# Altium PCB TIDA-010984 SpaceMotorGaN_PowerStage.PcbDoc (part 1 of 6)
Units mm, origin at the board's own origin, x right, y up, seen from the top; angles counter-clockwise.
Board outline 177.8 x 152.4 mm, 8 copper layers (Top Layer, DC LINK Layer 2, GND Layer 3, 3V3 Layer 4, Layer 5, Layer 6, GND Layer 7, Bottom Layer), stack 1.554 mm thick; 582 components, 280 nets, 1847 pads, 979 vias.
Unrouted connection lines stored in the file: 474.
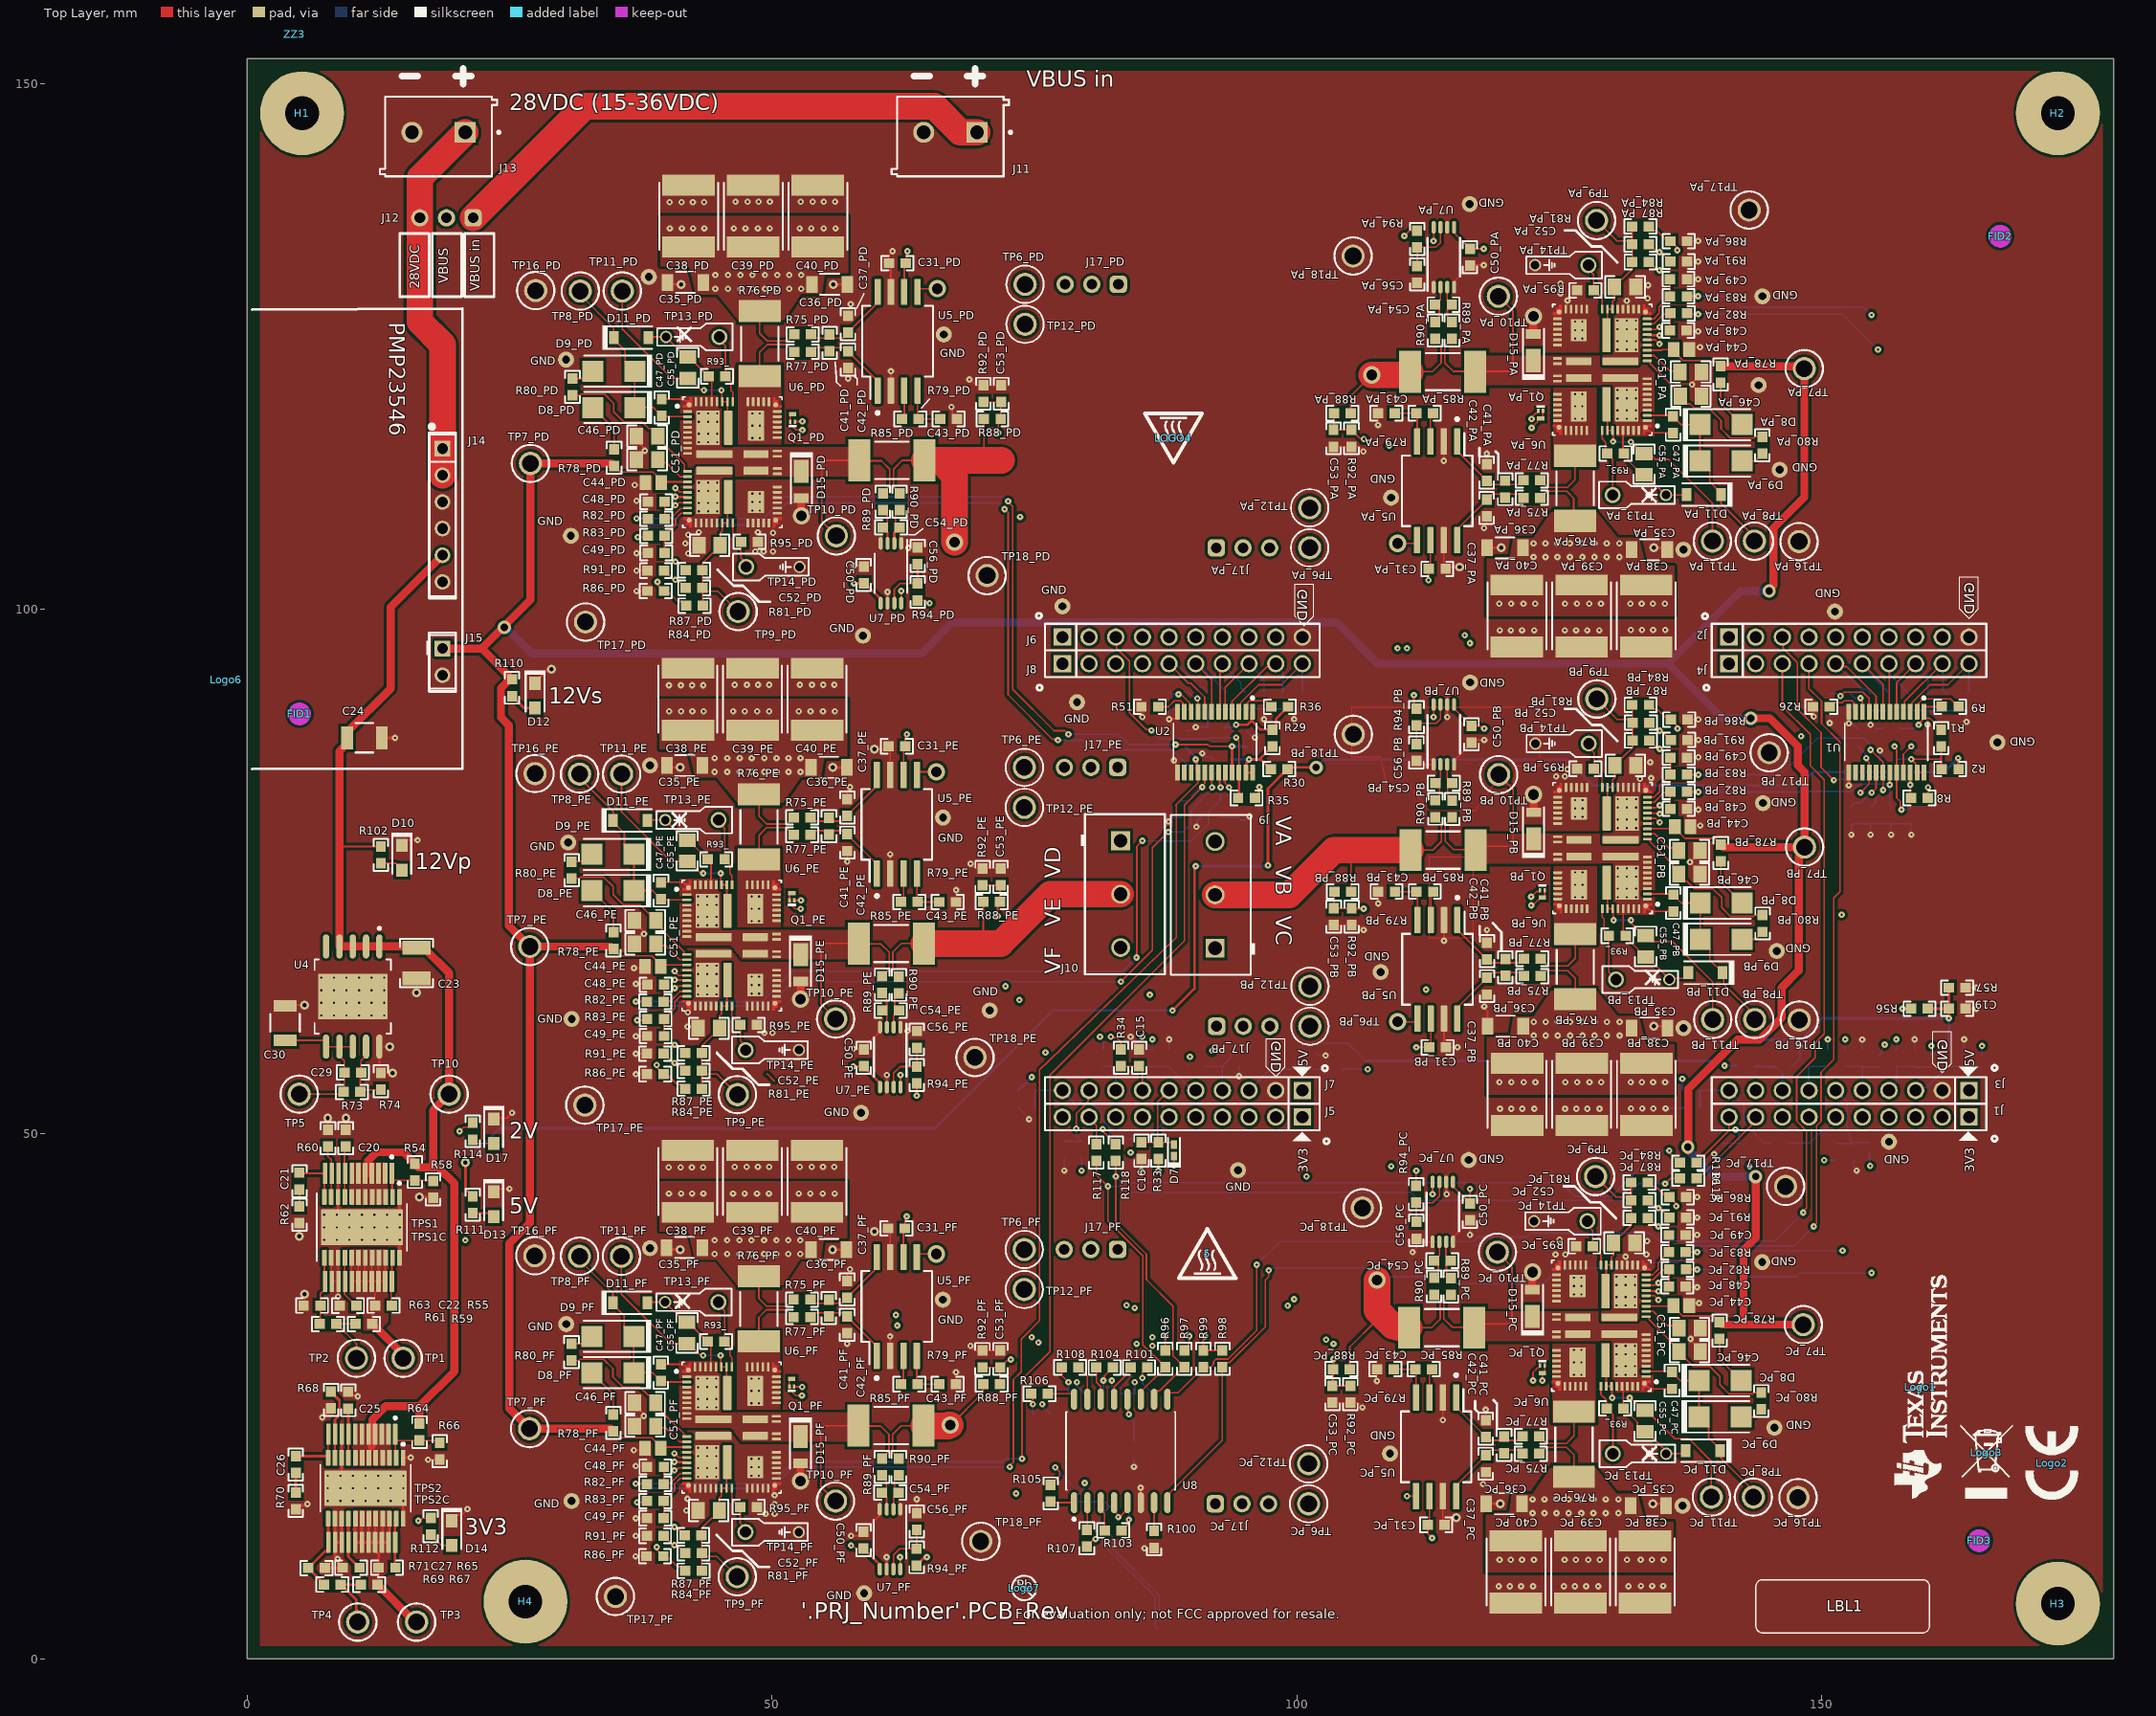
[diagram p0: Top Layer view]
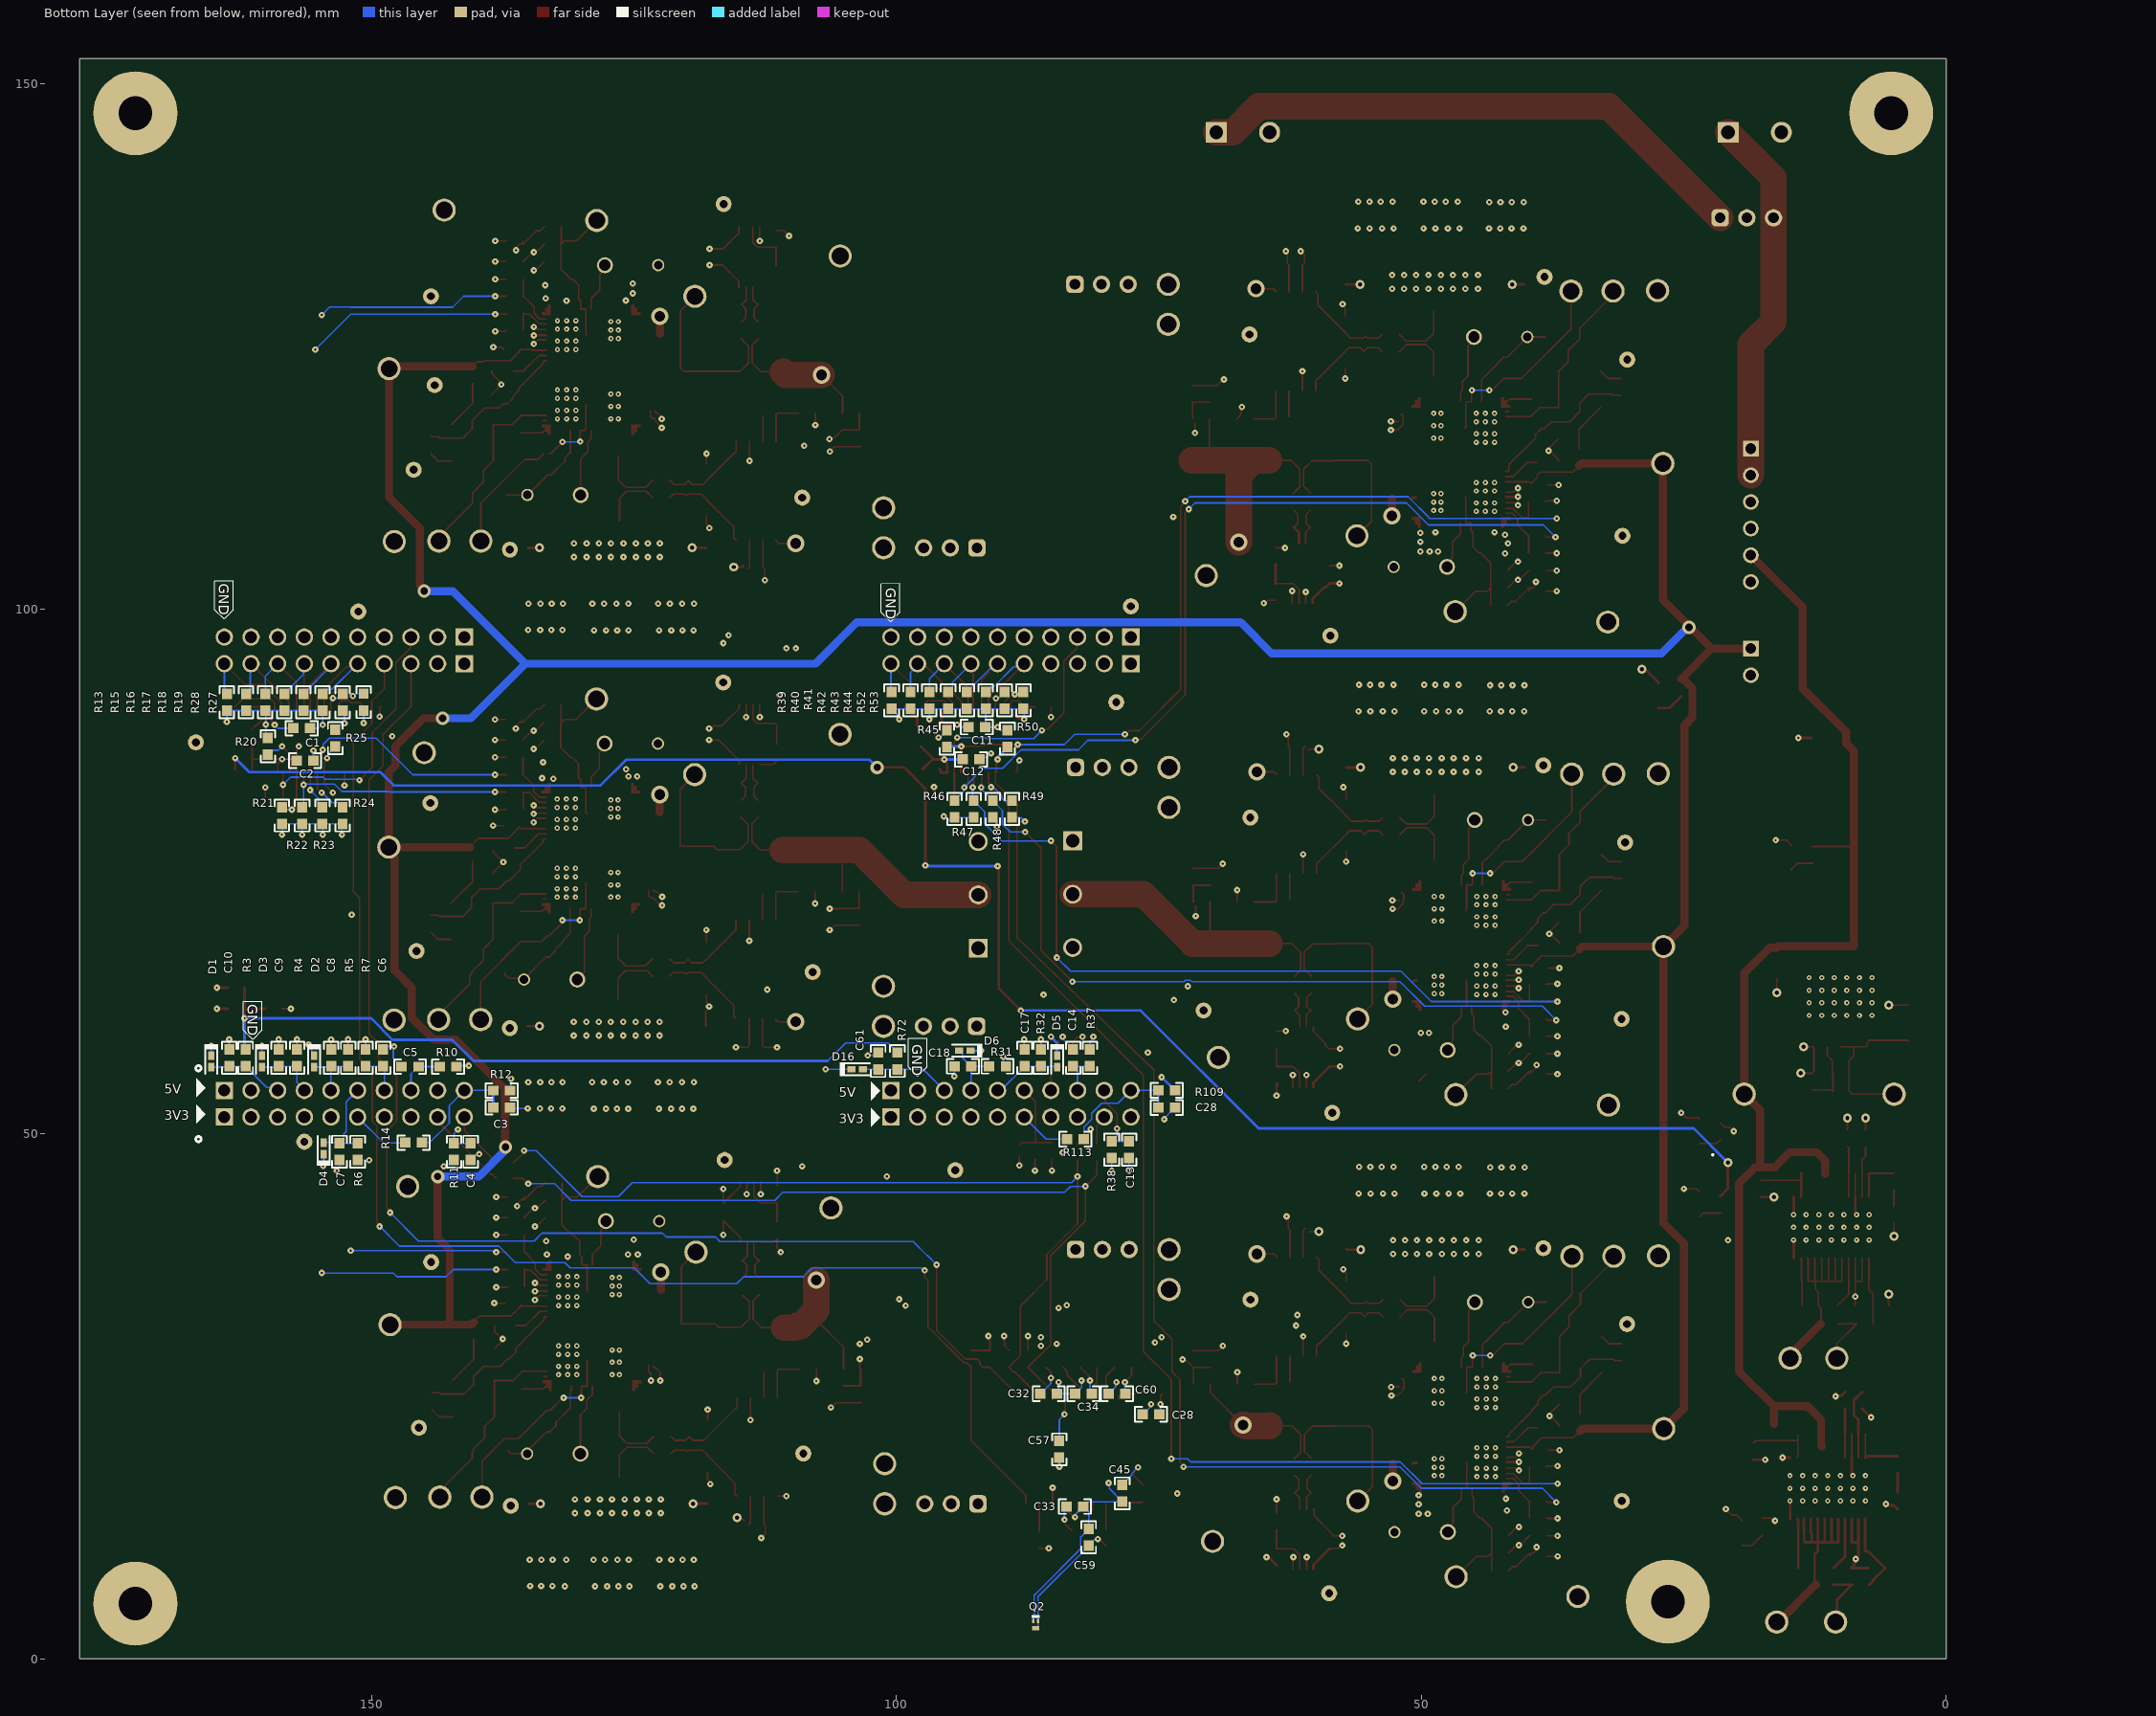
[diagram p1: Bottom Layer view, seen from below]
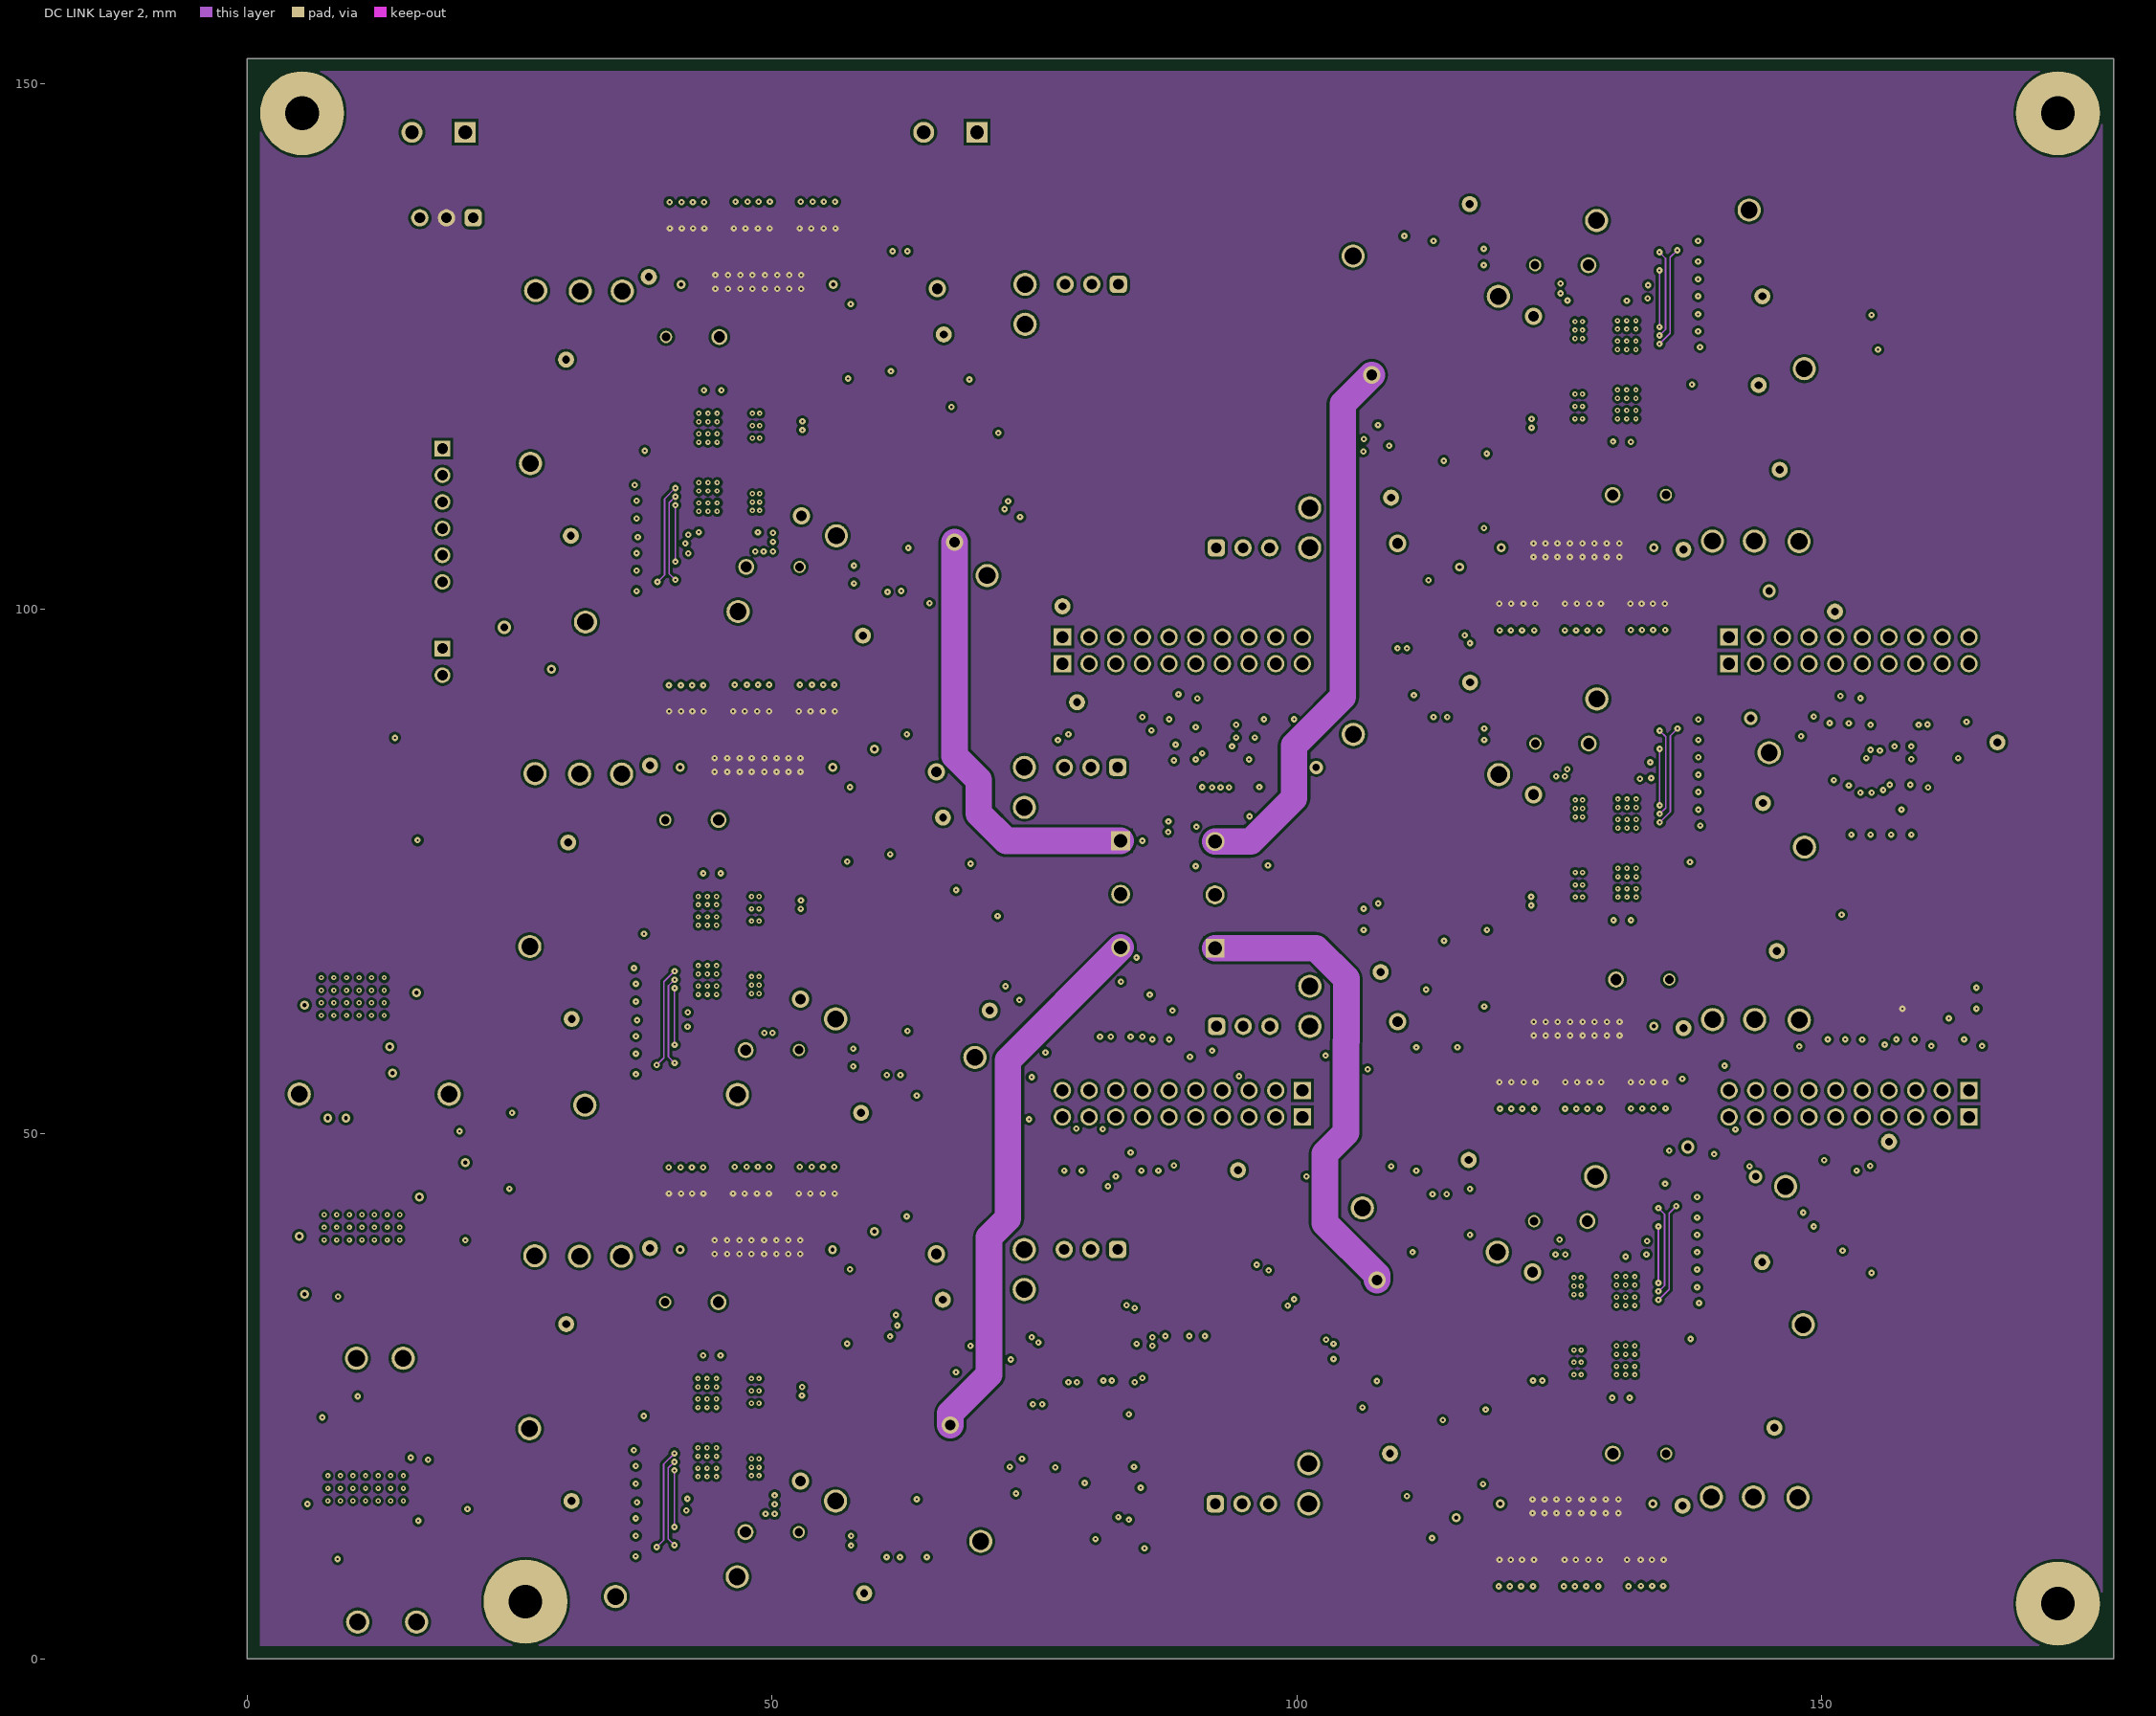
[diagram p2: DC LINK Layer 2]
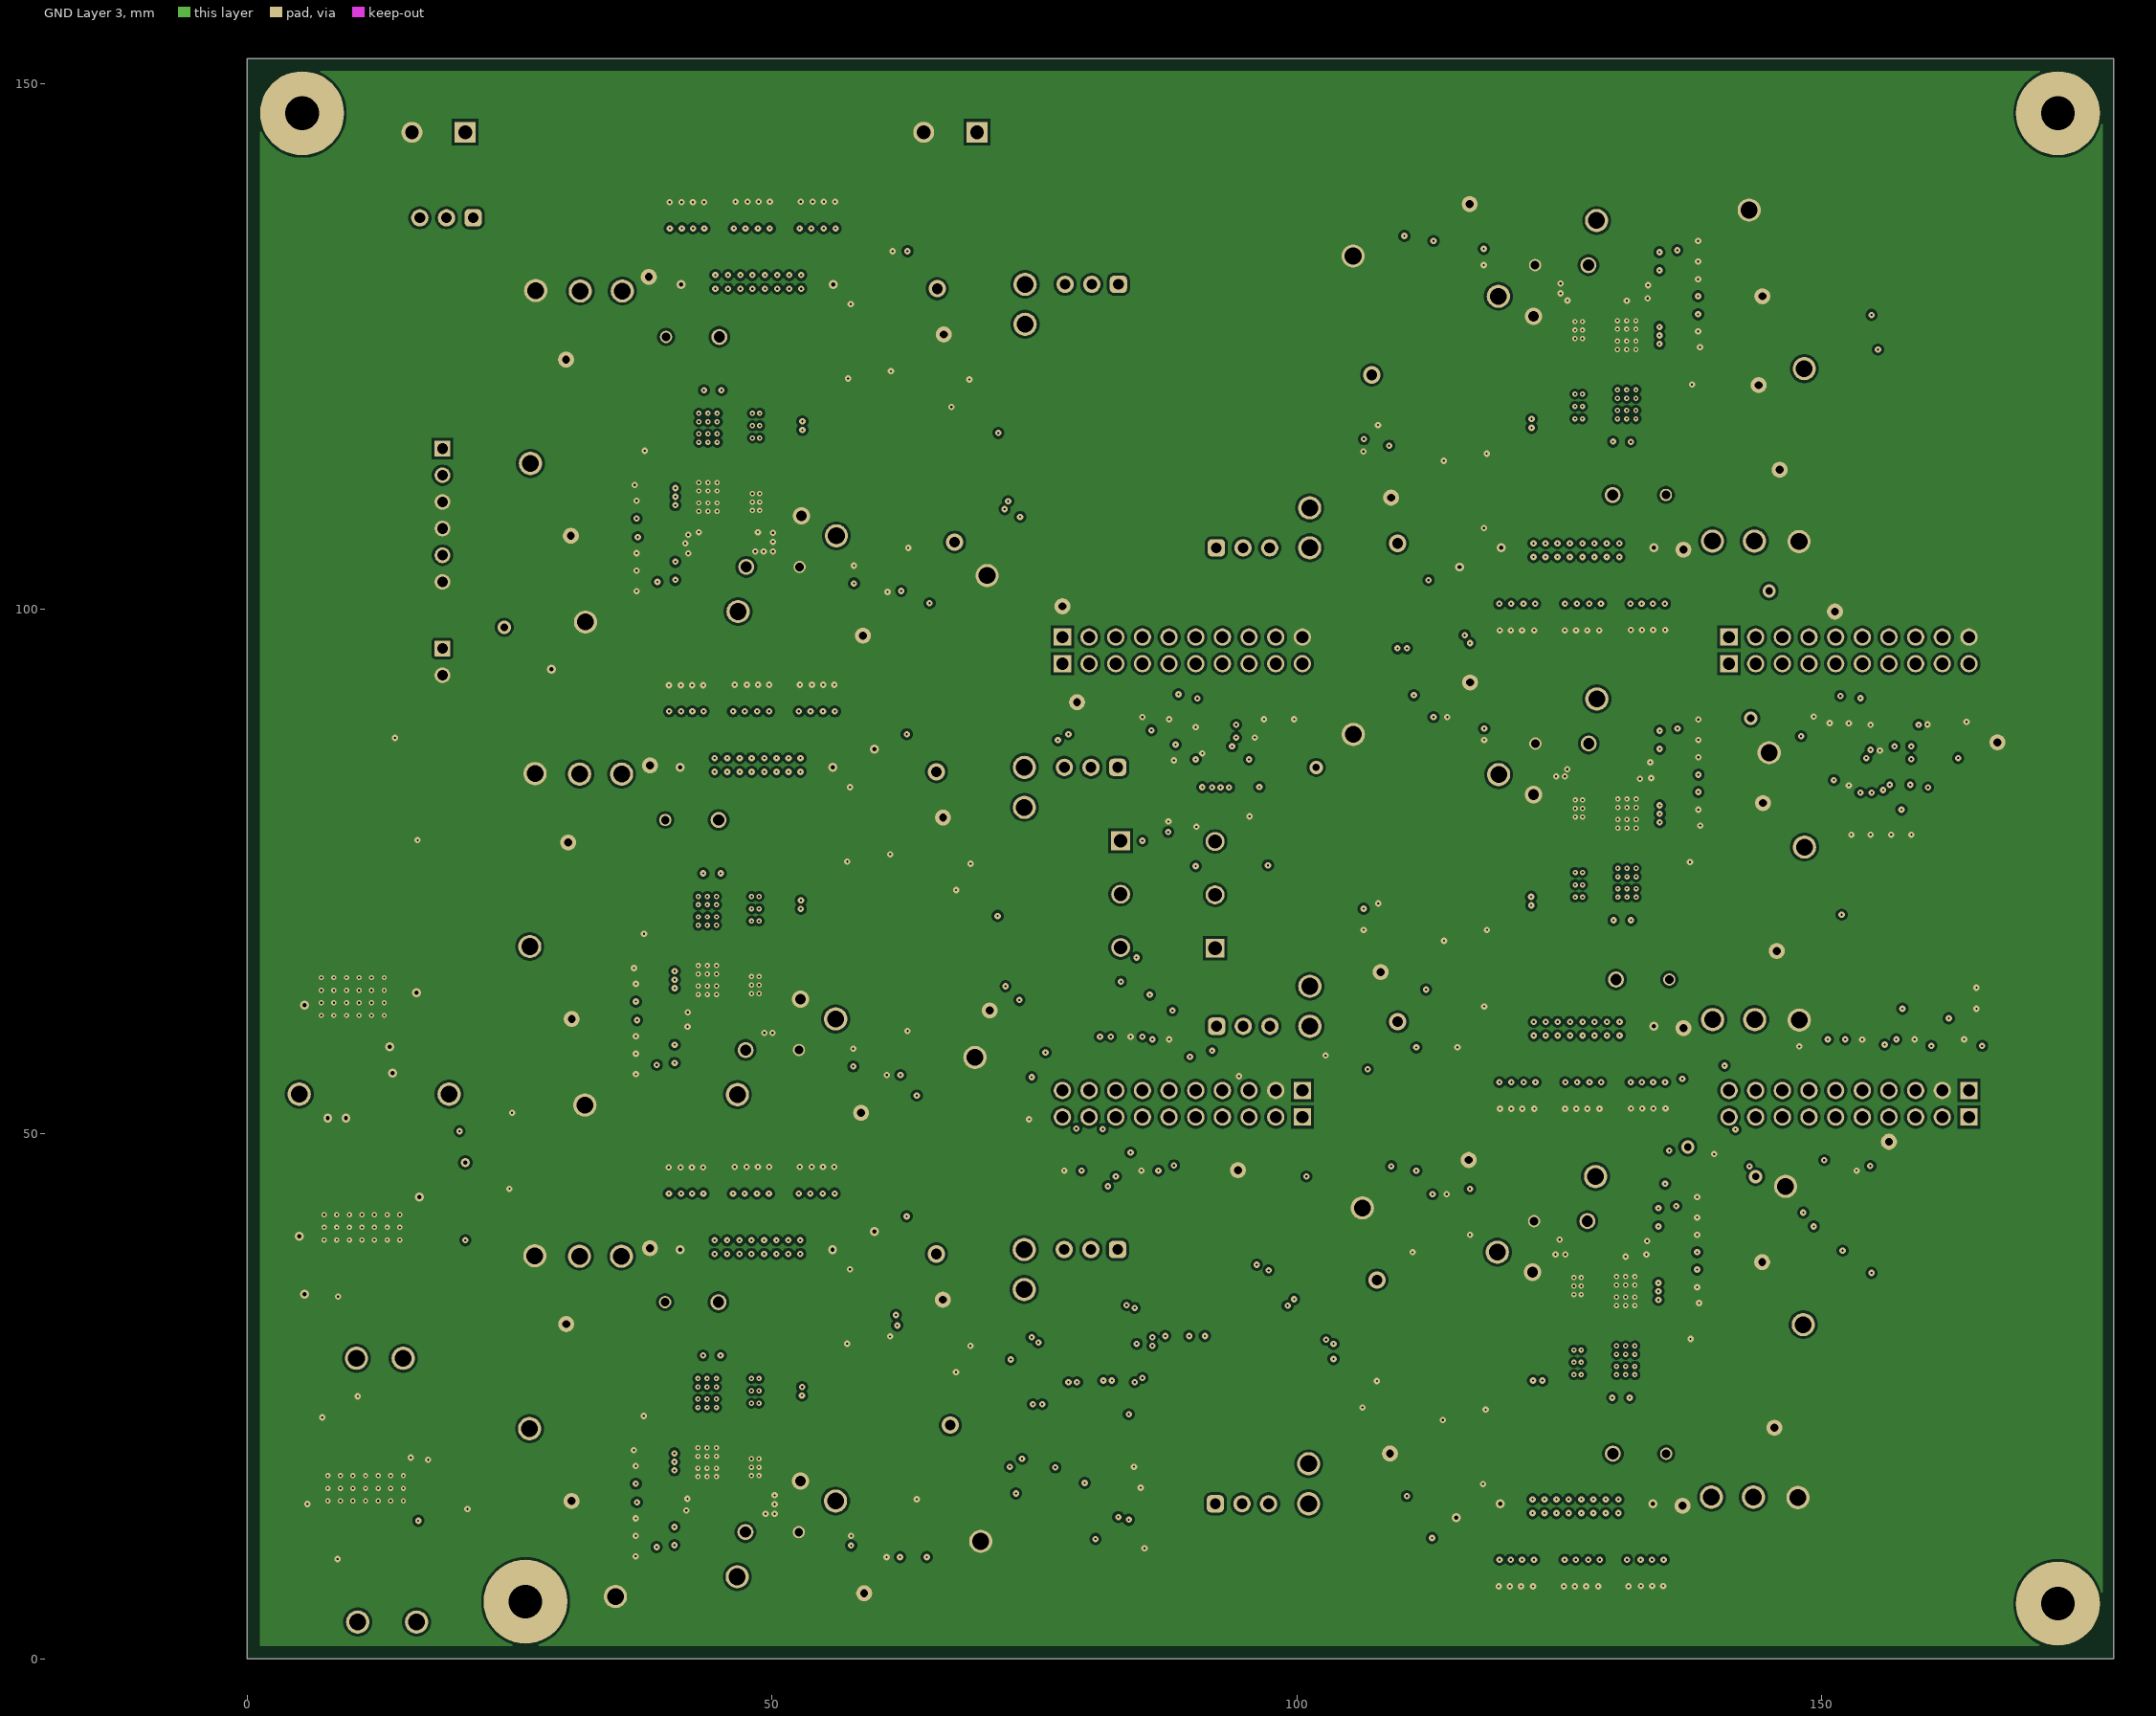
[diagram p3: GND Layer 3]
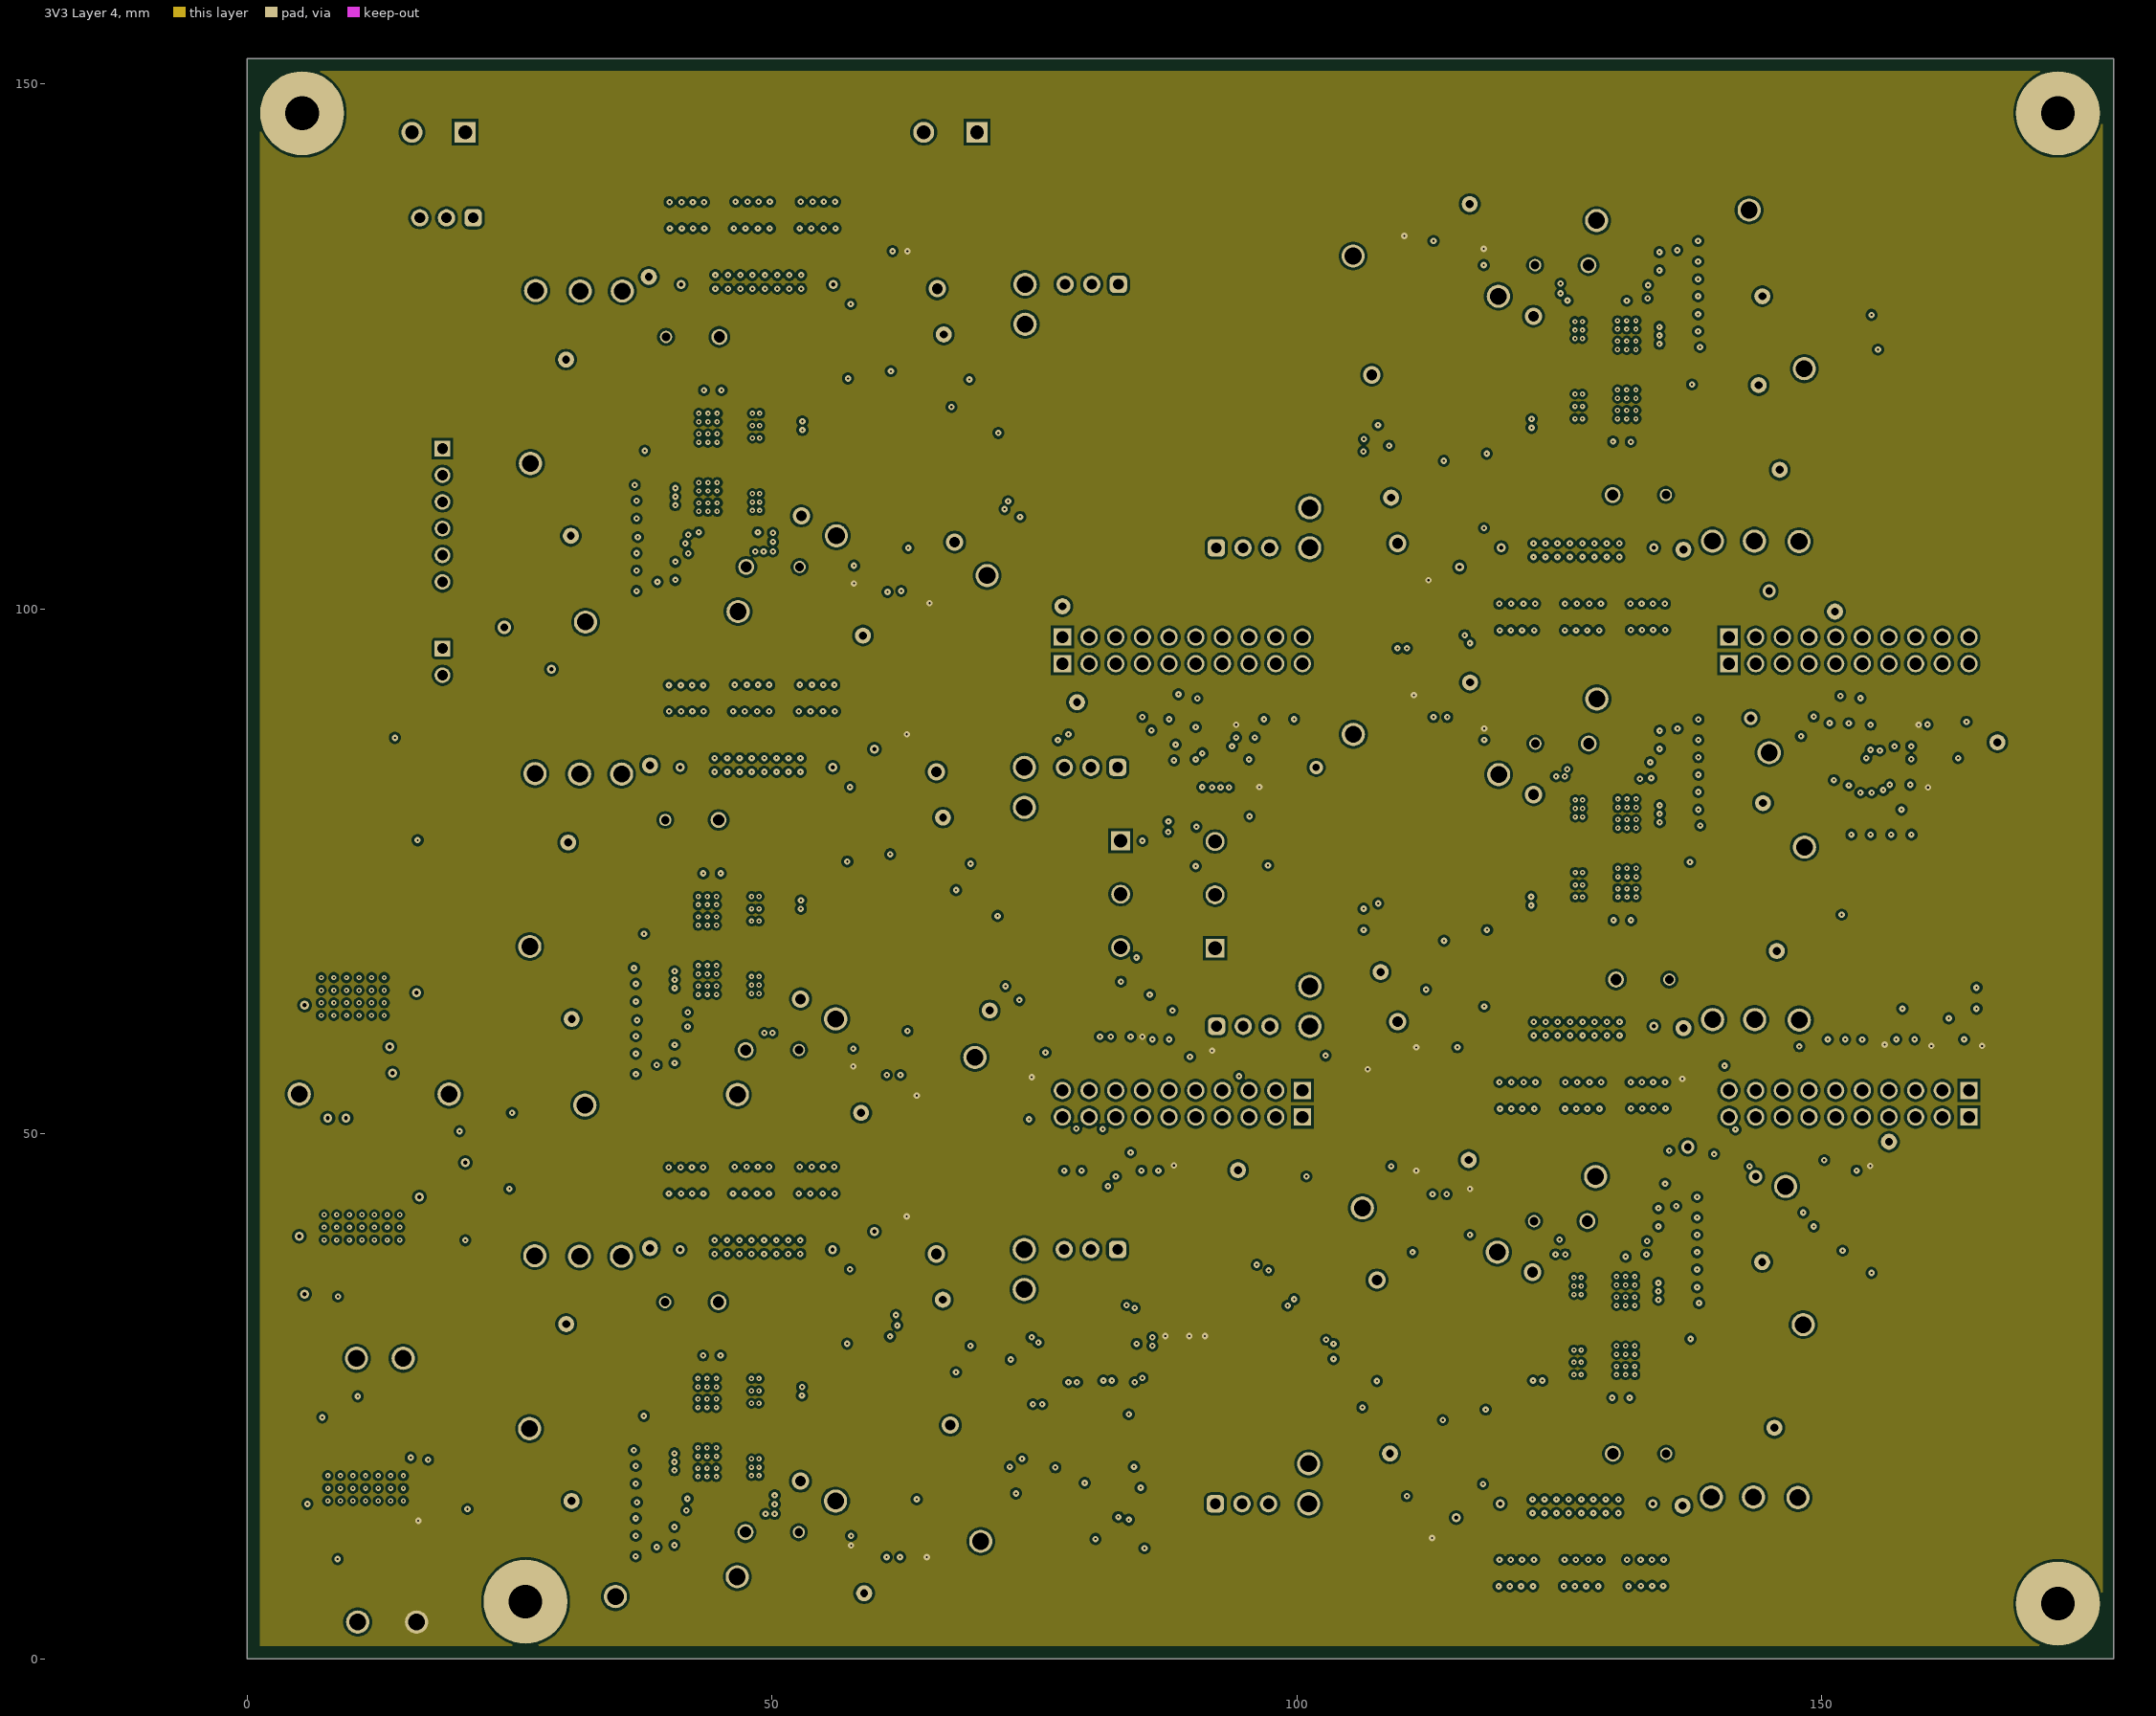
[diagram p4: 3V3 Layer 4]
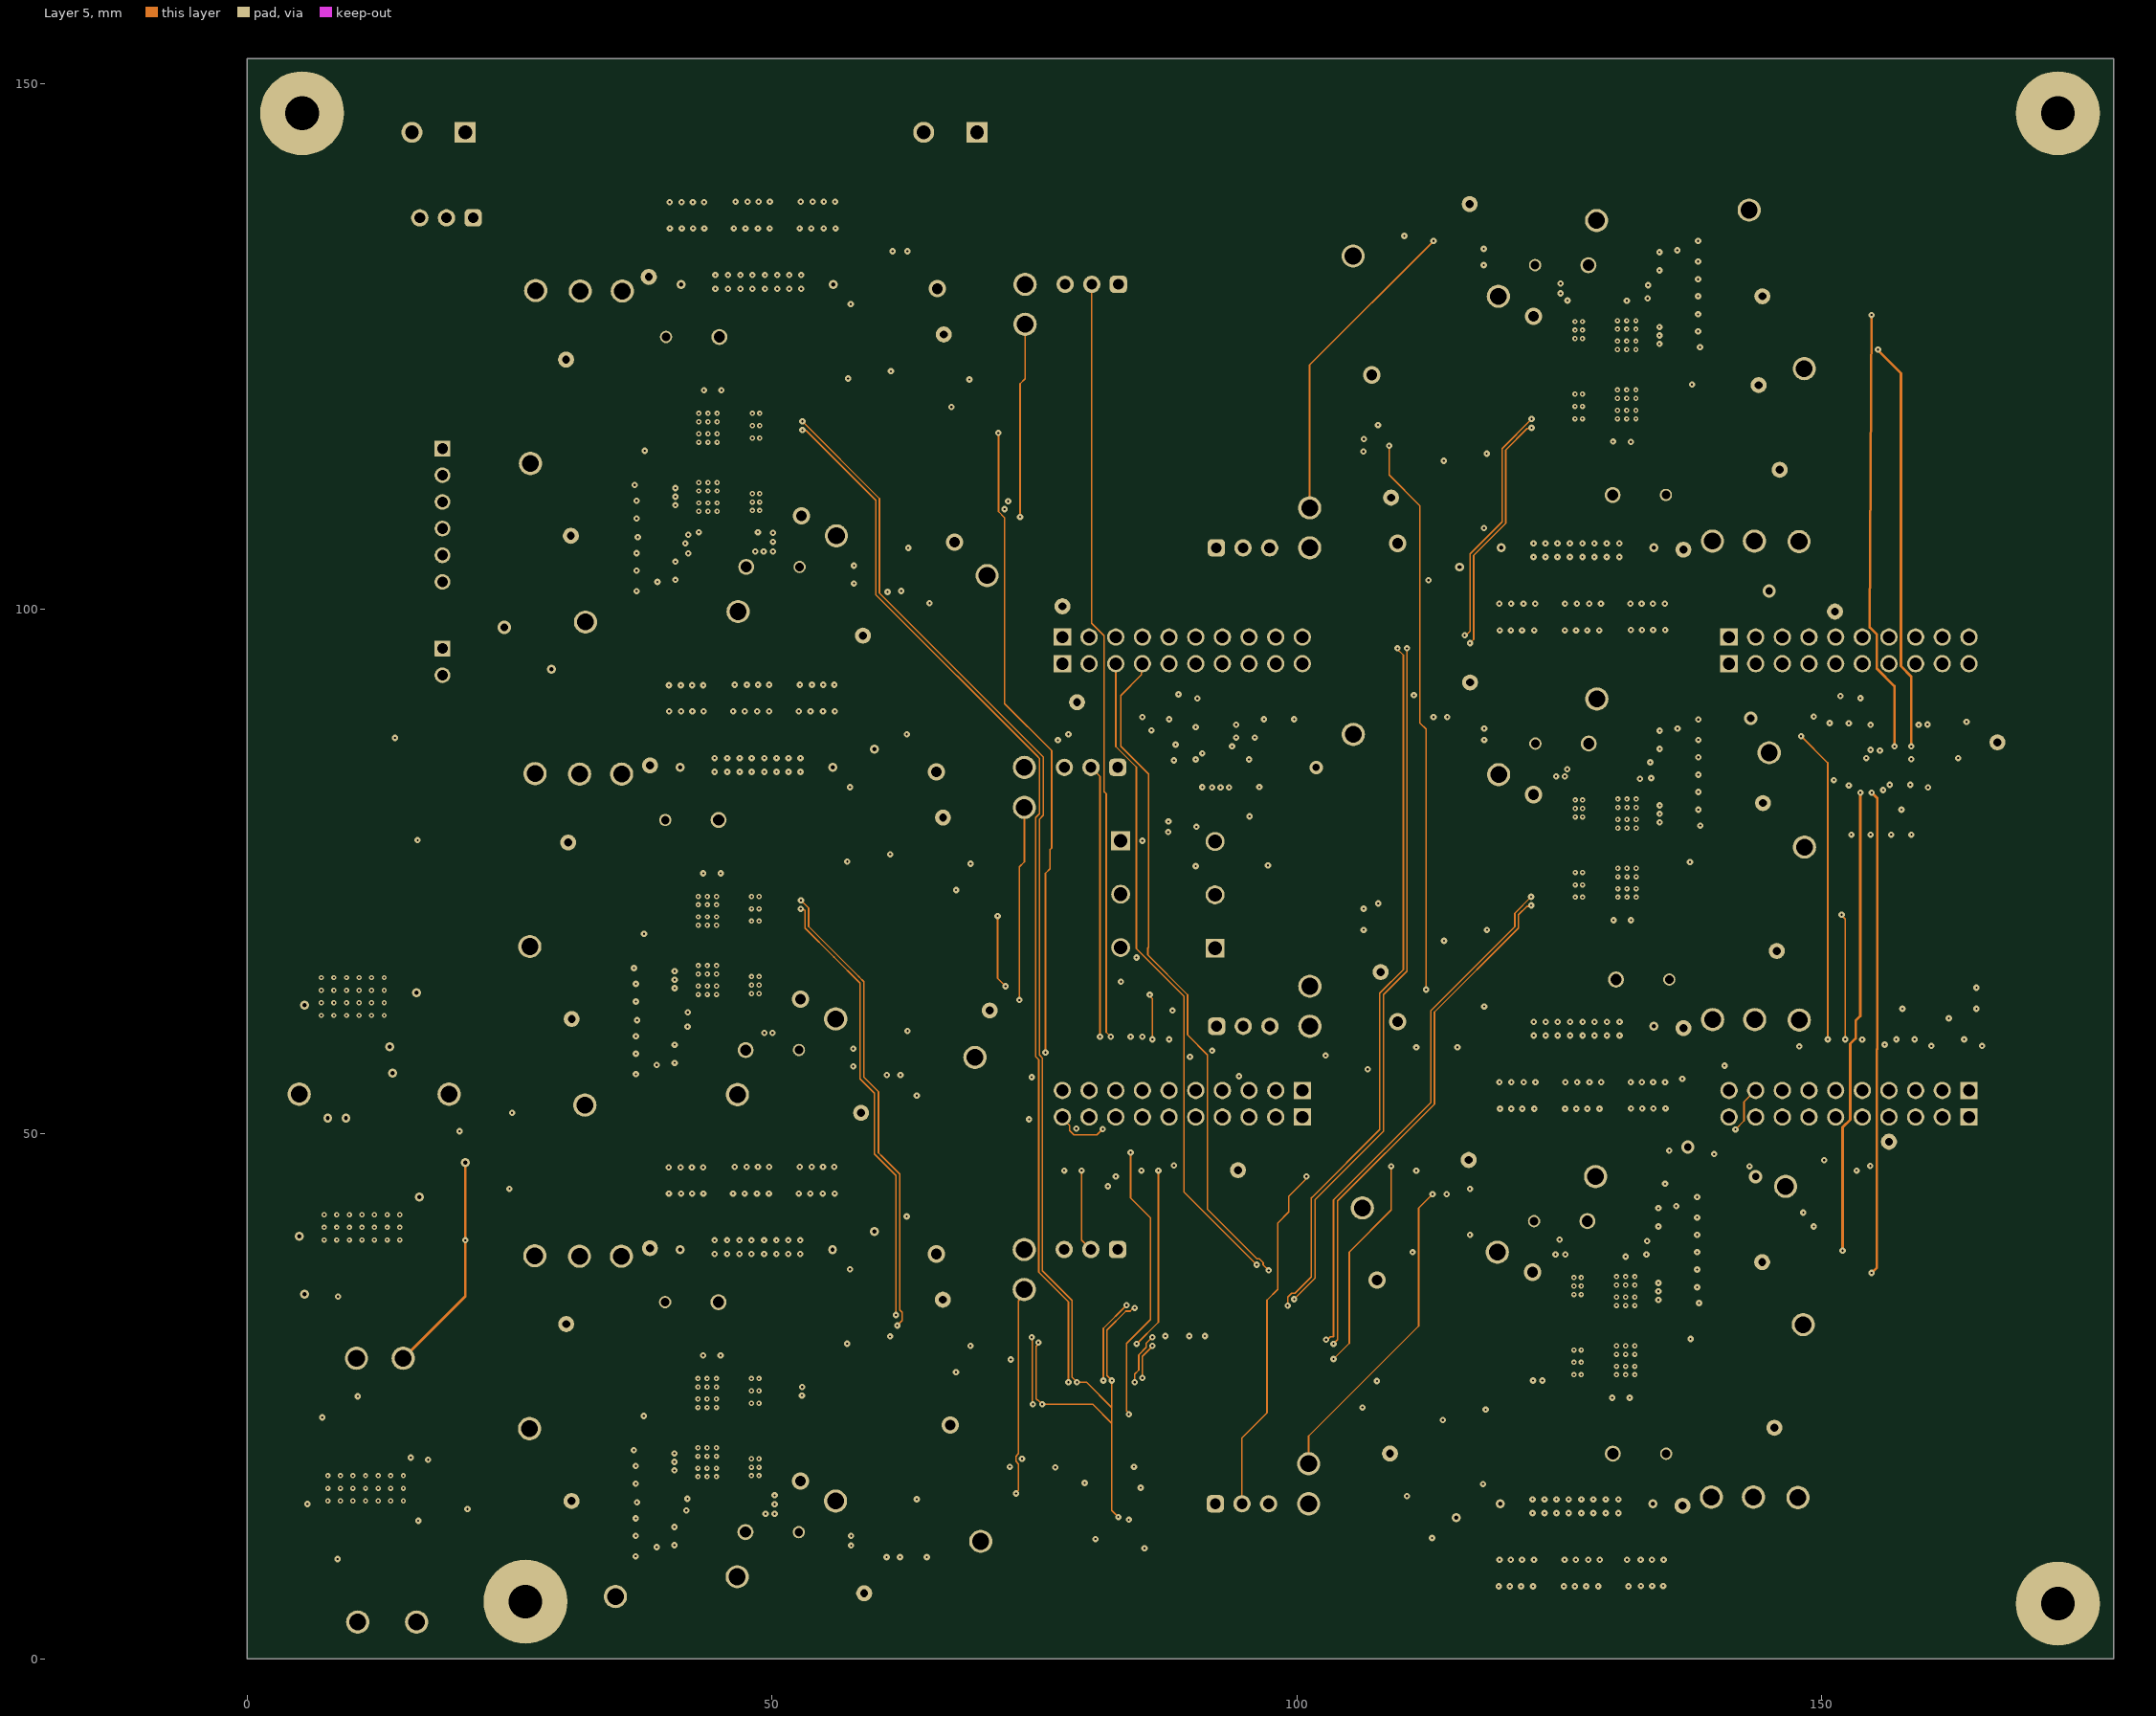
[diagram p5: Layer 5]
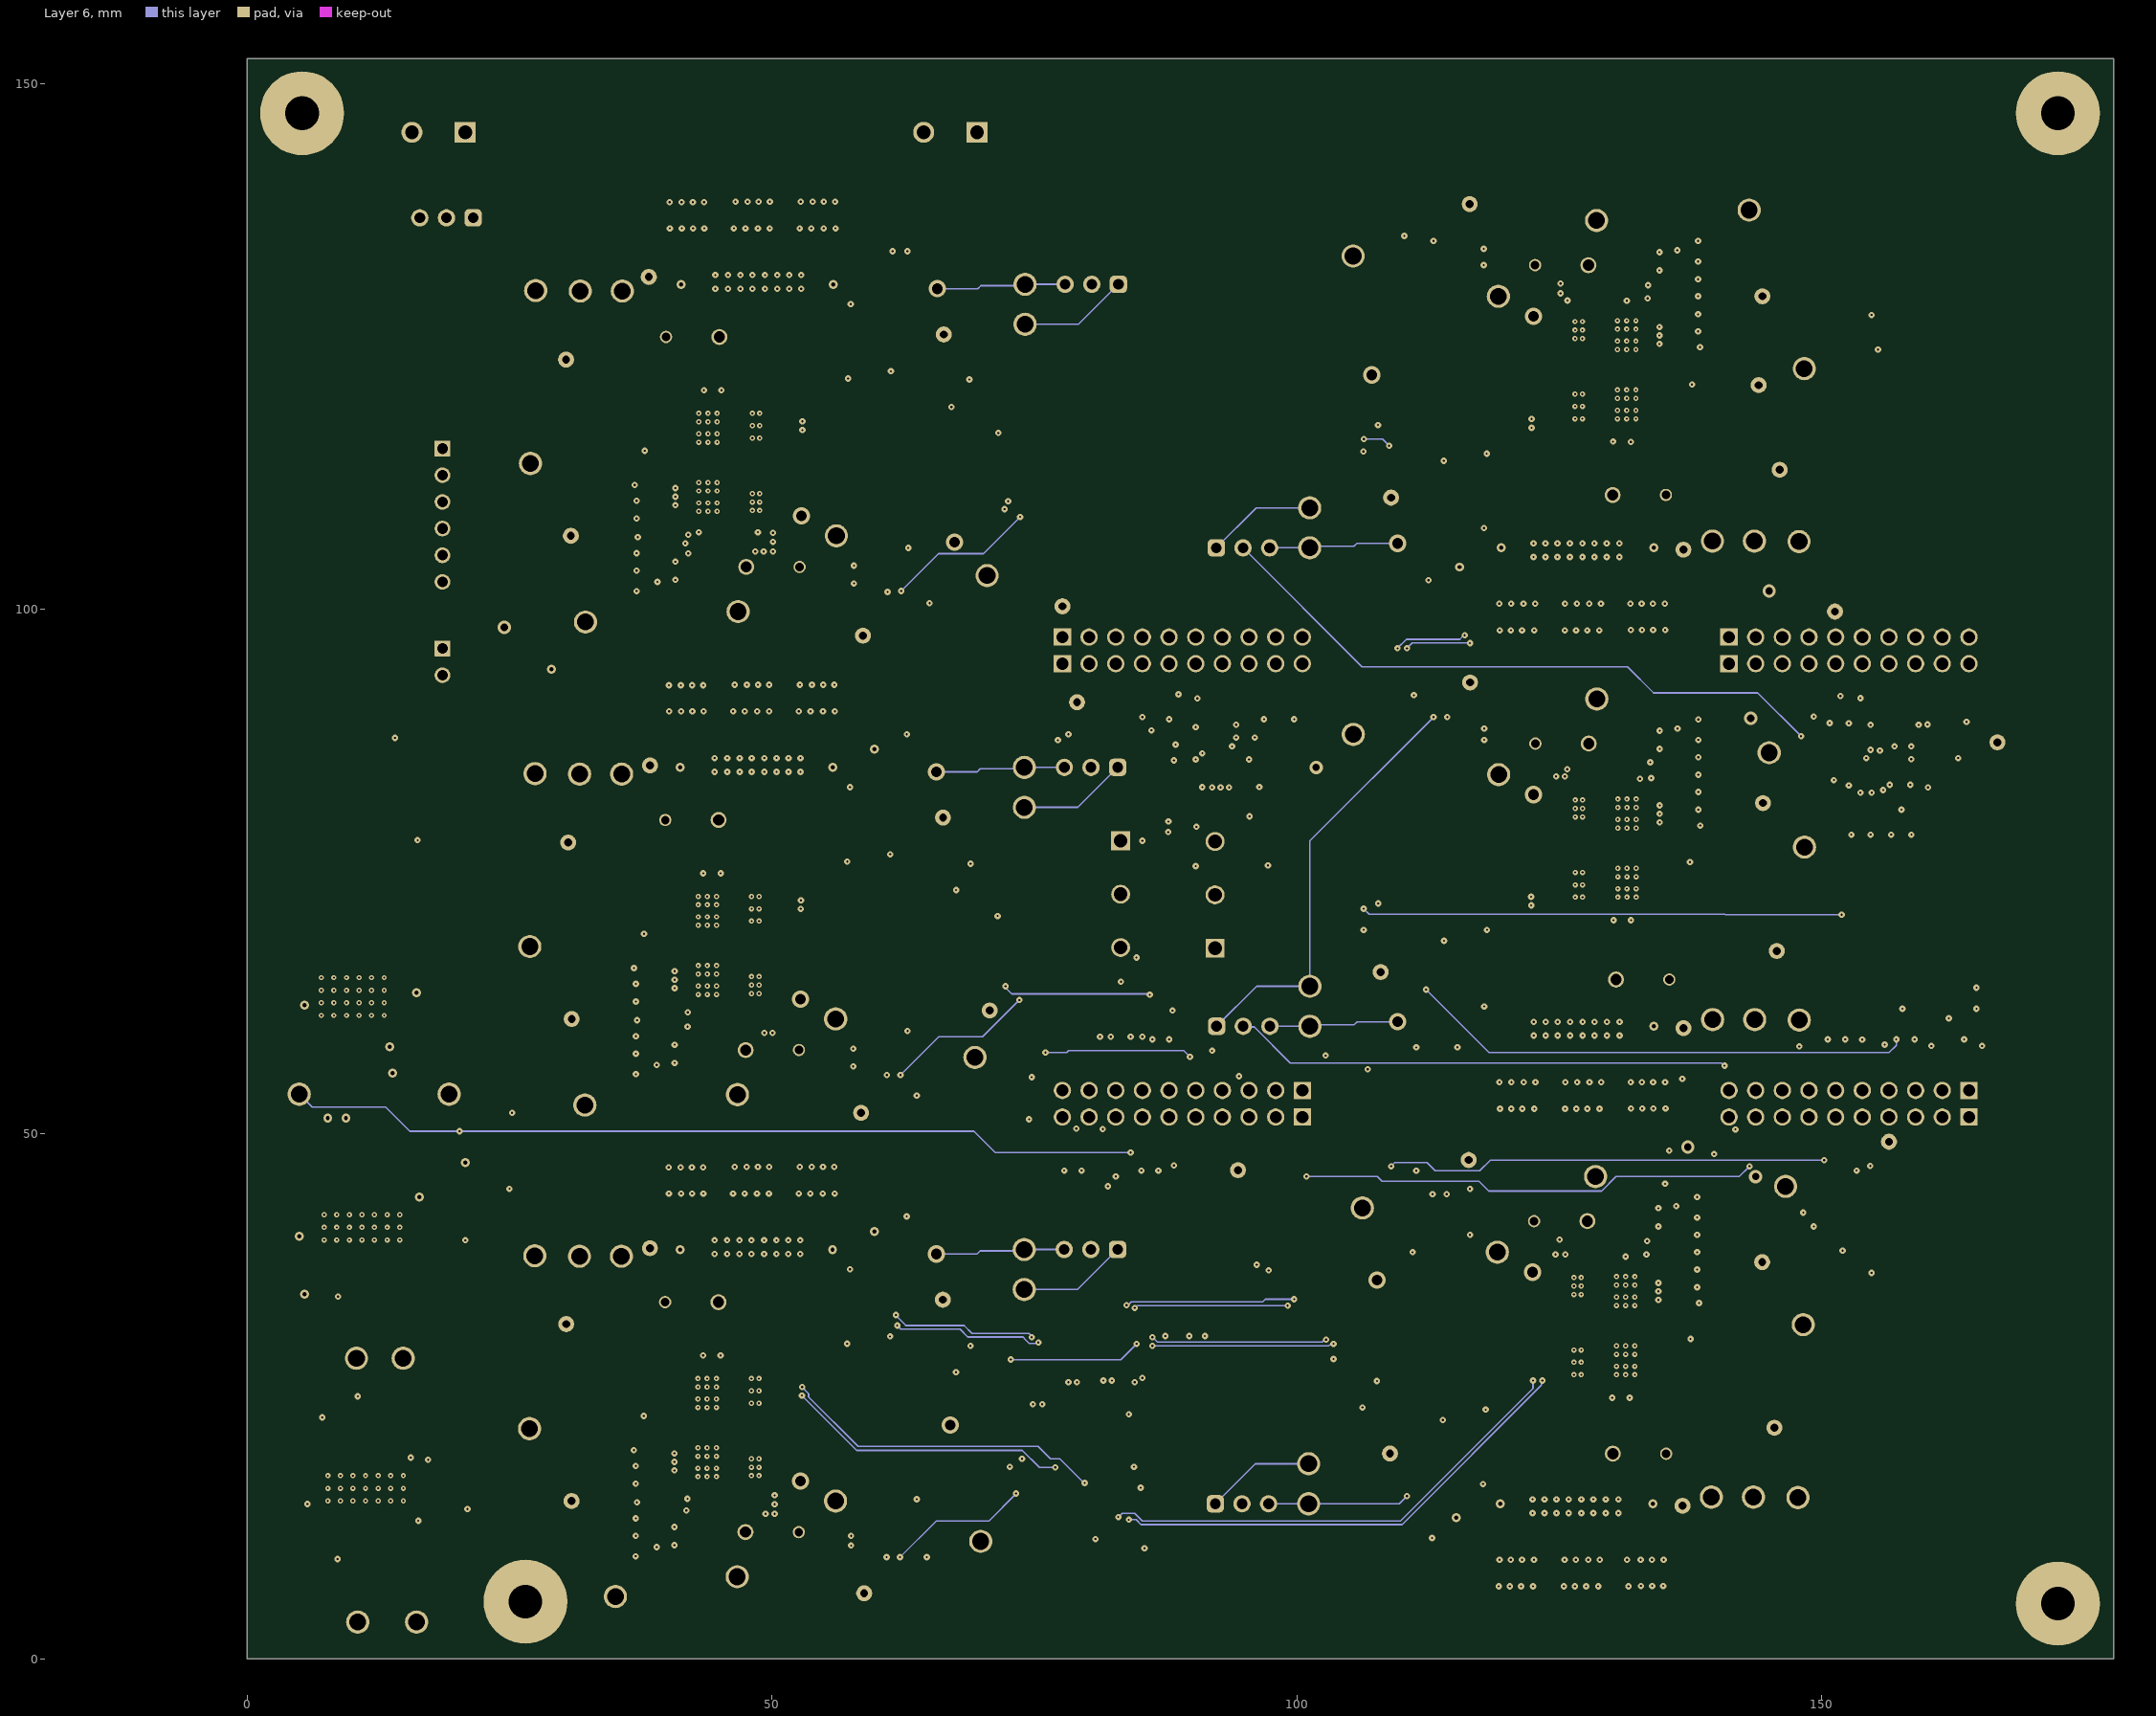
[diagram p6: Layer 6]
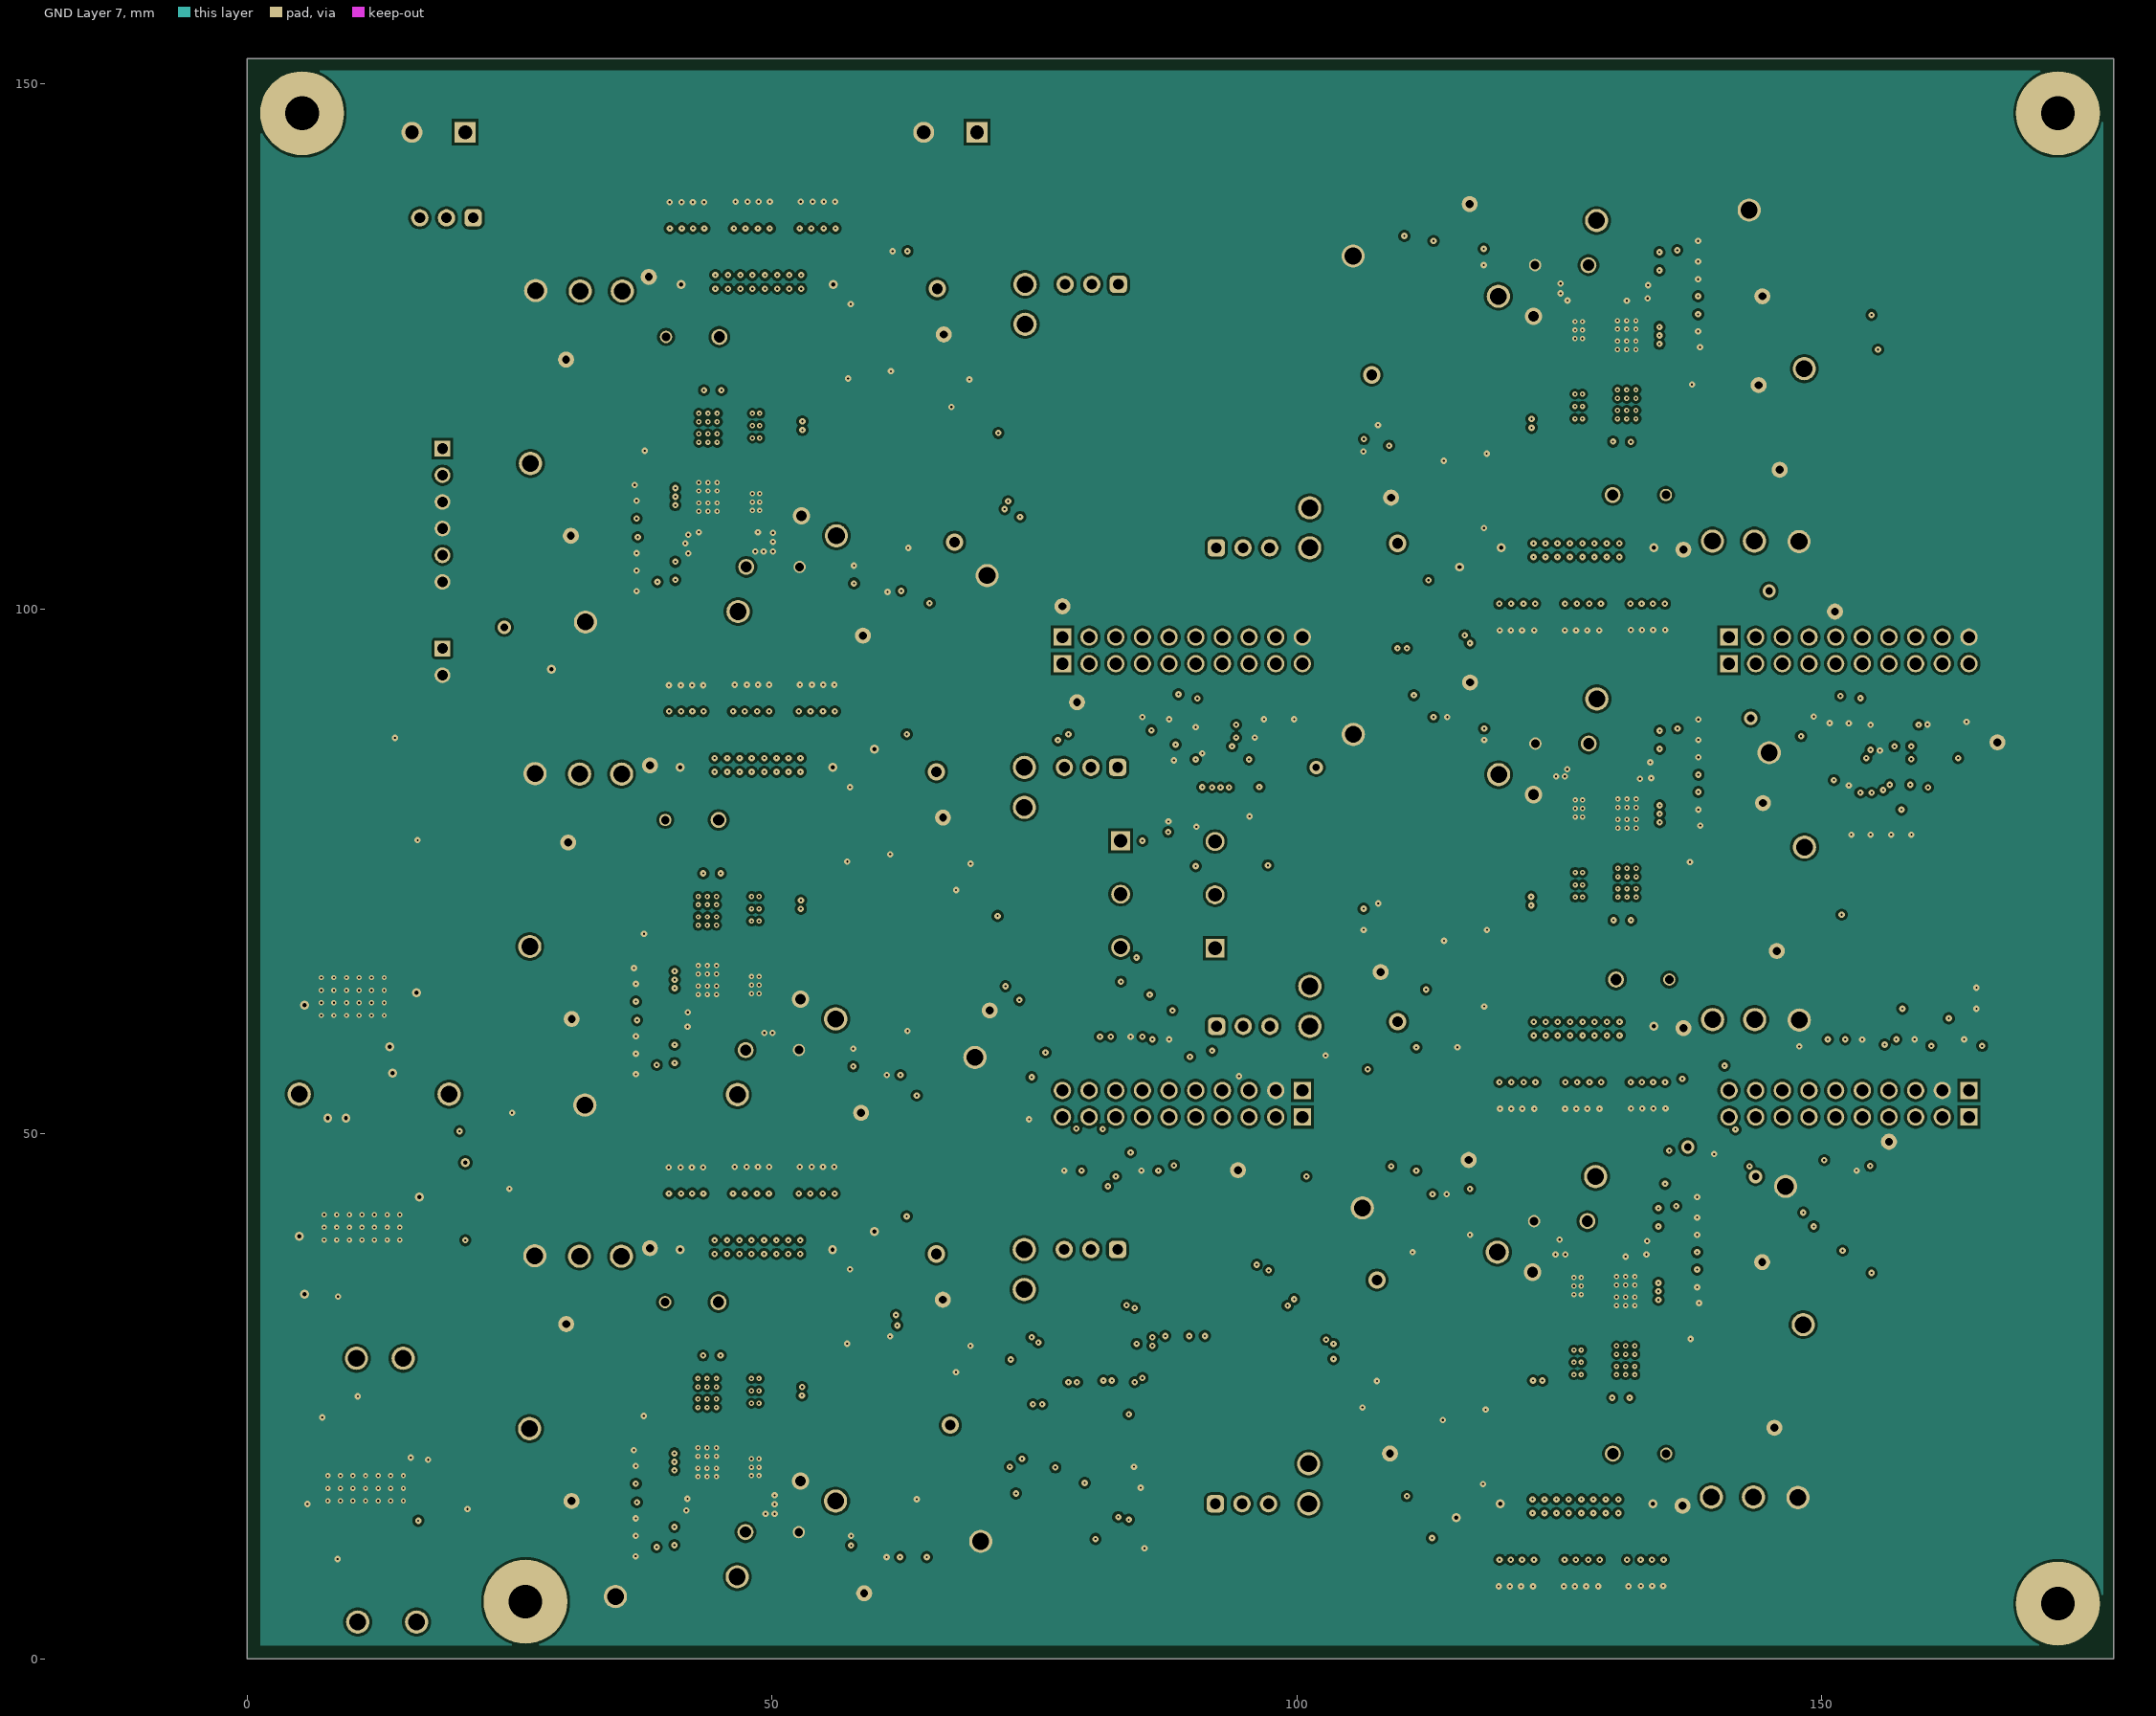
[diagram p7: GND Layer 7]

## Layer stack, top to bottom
Top Solder: solder mask 0.0102, Solder Resist, Dk 3.5
Top Layer: signal copper 0.035
Dielectric 1: prepreg 0.0711, PP-006, Dk 4.1
DC LINK Layer 2: signal copper 0.035
Dielectric 2: prepreg 0.0711, PP-006, Dk 4.1
GND Layer 3: signal copper 0.035
Dielectric 8: prepreg 0.0711, PP-006, Dk 4.1
3V3 Layer 4: signal copper 0.035
Dielectric 4: core 0.8478, FR-4 High Tg, Dk 4.8
Layer 5: signal copper 0.035
Dielectric 5: prepreg 0.0711, PP-006, Dk 4.1
Layer 6: signal copper 0.035
Dielectric 6: prepreg 0.0711, PP-006, Dk 4.1
GND Layer 7: signal copper 0.035
Dielectric 7: prepreg 0.0711, PP-006, Dk 4.1
Bottom Layer: signal copper 0.035
Bottom Solder: solder mask 0.0102, Solder Resist, Dk 3.5

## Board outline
0,0 177.8,0 177.8,152.4 0,152.4

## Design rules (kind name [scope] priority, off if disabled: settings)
AcuteAngle [All] p1: minimum=4.50000000000000E+0001 checktracksonly=FALSE
AssemblyTestPointUsage [All] p1: valid=2
BoardOutlineClearance BoardOutlineClearance_MountingHoles [OnCopper and InComponentClass('Mounting Holes')] p1: gap=1 ignorepadtopadclearanceinfootprint=FALSE
BoardOutlineClearance BoardOutlineClearance_Poly [OnCopper and IsPoly] p2: gap=0.635 ignorepadtopadclearanceinfootprint=FALSE
BoardOutlineClearance [OnCopper and Not InComponentClass('Logo') and not InComponentClass('FiducialMark') and not InRegion(1000,500,4000,800) and not InPoly] p3: gap=1.016 ignorepadtopadclearanceinfootprint=FALSE
Clearance Clearance_1 [InNamedPolygon('TOP_LAYER_NONET_P000')] p1: gap=0.254 ignorepadtopadclearanceinfootprint=TRUE except(0: Arc-Hole Track-Hole SMDPad-Hole THPad-Hole Via-Hole Fill-Hole Poly-Hole Region-Hole Text-Hole)
Clearance Clearance_Keepouts [((IsTrack Or IsArc) And Not InPoly) And IsFree and IsKeepOut vs ((IsTrack Or IsArc) And Not InPoly) And IsFree and IsKeepOut] p2: gap=0 ignorepadtopadclearanceinfootprint=FALSE
Clearance Clearance_Poly [InPolygon] p3: gap=0.254 ignorepadtopadclearanceinfootprint=TRUE
Clearance Clearance_FiducialMark [IsKeepOut and InComponentClass('FiducialMark') vs IsPad and InComponentClass('FiducialMark')] p4: gap=0 ignorepadtopadclearanceinfootprint=FALSE
Clearance [All] p5: gap=0.2 ignorepadtopadclearanceinfootprint=TRUE
ComponentClearance ComponentClearance_MountingHoles_FiducialMarks [InComponentClass('Mounting Holes') vs InComponentClass('FiducialMark')] p1: gap=1.27 collisioncheckmode=3 verticalgap=0.254 showdistances=FALSE
ComponentClearance ComponentClearance_Shunt [InComponentClass('Header') vs InComponentClass('Shunt')] p2: gap=0 collisioncheckmode=3 verticalgap=0 showdistances=FALSE
ComponentClearance ComponentClearance_Logo [InComponentClass('Logo')] p3: gap=0.762 collisioncheckmode=3 verticalgap=0.254 showdistances=FALSE
ComponentClearance ComponentClearance_ScrewToNut [(HasFootprint('NY PMS 440 0025 PH')) vs (HasFootprint('Keystone_1902C'))] p4: gap=0.127 collisioncheckmode=3 verticalgap=0.254 showdistances=FALSE
ComponentClearance ComponentClearance_MountingHoles [InComponentClass('Mounting Holes')] p5: gap=2.54 collisioncheckmode=3 verticalgap=2540 showdistances=FALSE
ComponentClearance ComponentClearance_SmallPassives [HasFootprint('0201*') or HasFootprint('0402*') or HasFootprint('0508') or HasFootprint('0603*') or HasFootprint('0612') or HasFootprint('0805*') or HasFootprint('0815*') or HasFootprint('0830*') or HasFootprint('1206*') or HasFootprint('1210*') or HasFootprint('1808*') or HasFootprint('1812*') or HasFootprint('1825*') or HasFootprint('2010*') or HasFootprint('2220*') or HasFootprint('2225*') or HasFootprint('2512*') or HasFootprint('2728*') or HasFootprint('3518*') vs HasFootprint('0201*') or HasFootprint('0402*') or HasFootprint('0508') or HasFootprint('0603*') or HasFootprint('0612') or HasFootprint('0805*') or HasFootprint('0815*') or HasFootprint('0830*') or HasFootprint('1206*') or HasFootprint('1210*') or HasFootprint('1808*') or HasFootprint('1812*') or HasFootprint('1825*') or HasFootprint('2010*') or HasFootprint('2220*') or HasFootprint('2225*') or HasFootprint('2512*') or HasFootprint('2728*') or HasFootprint('3518*')] p6: gap=0.38 collisioncheckmode=3 verticalgap=0.254 showdistances=FALSE
ComponentClearance ComponentClearance_THtoSMT [IsThruComponent vs IsSMTComponent] p7: gap=0.762 collisioncheckmode=3 verticalgap=0.762 showdistances=FALSE
ComponentClearance ComponentClearance_THtoTH [IsThruComponent vs IsThruComponent] p8: gap=0.508 collisioncheckmode=3 verticalgap=0.762 showdistances=FALSE
ComponentClearance [All] p9: gap=0.508 collisioncheckmode=3 verticalgap=0.254 showdistances=FALSE
DiffPairsRouting [All] p1: maxlimit=2.54 minlimit=0.254 mostfreqgap=0.254 toplayer_minwidth=0.381 toplayer_maxwidth=0.381 toplayer_prefwidth=0.381 midlayer1_minwidth=0.381 midlayer1_maxwidth=0.381 midlayer1_prefwidth=0.381 midlayer2_minwidth=0.381 midlayer2_maxwidth=0.381 midlayer2_prefwidth=0.381 midlayer3_minwidth=0.381 midlayer3_maxwidth=0.381 midlayer3_prefwidth=0.381 midlayer4_minwidth=0.381 midlayer4_maxwidth=0.381 midlayer4_prefwidth=0.381 midlayer5_minwidth=0.381 midlayer5_maxwidth=0.381 midlayer5_prefwidth=0.381 midlayer6_minwidth=0.381 midlayer6_maxwidth=0.381 midlayer6_prefwidth=0.381 bottomlayer_minwidth=0.381 bottomlayer_maxwidth=0.381 bottomlayer_prefwidth=0.381 maxuncoupledlength=25.4
FabricationTestPointUsage TestPointUsage [All] p1: valid=2 allowmultiple=FALSE
FabricationTestpoint Testpoint [All] p1: side=3 testpointundercomponent=TRUE minsize=1.016 maxsize=2.54 preferedsize=1.524 minholesize=0 maxholesize=1.016 preferedholesize=0.813 testpointgrid=0.025 allowsidetop=TRUE allowsidebottom=TRUE usegrid=TRUE gridtolerance=0
FanoutControl Fanout_LCC [IsLCC] p1: bgadir=Out bgaviamode=Centered fanoutstyle=Auto fanoutdirection=Alternating viagrid=0.025 // Fanout_LCC (Default Rule)
FanoutControl Fanout_BGA [IsBGA] p2: bgadir=Out bgaviamode=Centered fanoutstyle=Auto fanoutdirection=Alternating viagrid=0.025 // Fanout_BGA (Default Rule)
FanoutControl Fanout_Default [All] p4: bgadir=Out bgaviamode=Centered fanoutstyle=Auto fanoutdirection=Alternating viagrid=0.025 // Fanout_Default (Default Rule)
FanoutControl Fanout_Small [(CompPinCount < 5)] p5: bgadir=Out bgaviamode=Centered fanoutstyle=Auto fanoutdirection=OutThenIn viagrid=0.025 // Fanout_Small (Default Rule)
HoleSize [All] p1: absolutevalues=TRUE maxlimit=6.375 minlimit=0.2 maxpercent=80.000 minpercent=20.000
MinimumAnnularRing MinimumAnnularRing_ThermalPadVias [IsVia and InAnyComponent] p1: minimumring=0.15
MinimumAnnularRing [All] p2: minimumring=0.2
MinimumSolderMaskSliver MinimumSolderMaskSliver_Logo [InComponentClass('Logo') vs InComponentClass('Logo')] p1: minsoldermaskwidth=0.018
MinimumSolderMaskSliver [All] p2: minsoldermaskwidth=0.1
PlaneConnect [All] p1: planeconnectstyle=Relief reliefexpansion=0.254 reliefentries=4 reliefconductorwidth=0.254 reliefairgap=0.254
PolygonConnect [All] p1: connectstyle=Direct reliefconductorwidth=0.254 reliefentries=4 polygonreliefangle="90 Angle" airgapwidth=0.254
RoomDefinition PF [InComponentClass('PF')] p1: confinementstyle=ConfineIn formatcopy=TRUE lockcomponents=FALSE outline 30.26,19.653 25.016,19.653 25.016,40.64 38.824,40.64 38.962,49.805 60.168,49.805 60.168,43.064 84.313,43.064 84.313,31.814 76.418,31.814 76.241,23.741 69.9,7.117 50.067,7.117 50.067,4.289 30.26,4.289
RoomDefinition PE [InComponentClass('PE')] p2: confinementstyle=ConfineIn formatcopy=FALSE lockcomponents=FALSE outline 30.274,65.577 25.03,65.577 25.03,86.564 38.838,86.564 38.976,95.729 60.182,95.729 60.182,88.988 84.327,88.988 84.327,77.738 76.432,77.738 76.254,69.665 69.913,53.041 50.08,53.041 50.08,50.213 30.274,50.213
RoomDefinition PD [InComponentClass('PD')] p3: confinementstyle=ConfineIn formatcopy=FALSE lockcomponents=FALSE outline 30.342,111.589 25.098,111.589 25.098,132.576 38.906,132.576 39.044,141.741 60.25,141.741 60.25,135 84.395,135 84.395,123.75 76.5,123.75 76.323,115.677 69.982,99.053 50.149,99.053 50.149,96.225 30.342,96.225
RoomDefinition PA [InComponentClass('PA')] p4: confinementstyle=ConfineIn formatcopy=FALSE lockcomponents=TRUE outline 145.006,125.155 150.25,125.155 150.25,104.168 136.442,104.168 136.304,95.003 115.098,95.003 115.098,101.744 90.953,101.744 90.953,112.994 98.848,112.994 99.025,121.066 104.649,135.961 125.261,136.052 125.199,140.519 145.006,140.519
RoomDefinition PC [InComponentClass('PC')] p5: confinementstyle=ConfineIn formatcopy=FALSE lockcomponents=FALSE outline 144.908,34.099 150.152,34.099 150.152,13.112 136.344,13.112 136.206,3.947 115,3.947 115,10.688 90.855,10.688 90.855,21.938 98.75,21.938 98.927,30.011 104.551,44.905 125.163,44.996 125.101,49.463 144.908,49.463
RoomDefinition PB [InComponentClass('PB')] p6: confinementstyle=ConfineIn formatcopy=FALSE lockcomponents=TRUE outline 145.028,79.586 150.272,79.586 150.272,58.599 136.464,58.599 136.326,49.434 115.12,49.434 115.12,56.175 90.975,56.175 90.975,67.425 98.87,67.425 99.048,75.498 104.671,90.392 125.283,90.483 125.222,94.95 145.028,94.95
RoomDefinition FiducialMark [InComponentClass('FiducialMark')] p7: confinementstyle=ConfineIn formatcopy=TRUE lockcomponents=FALSE outline 0.5,152.75 21.62,152.75 21.62,1.5 0.5,1.5
RoutingLayers [All] p1: top layer_v5=TRUE mid layer 1_v5=TRUE mid layer 2_v5=FALSE mid layer 3_v5=TRUE mid layer 4_v5=TRUE mid layer 5_v5=FALSE mid layer 6_v5=FALSE bottom layer_v5=TRUE
RoutingVias [All] p1: holewidth=0.406 width=0.864 viastyle="Through Hole" minholewidth=0.2 minwidth=0.5 maxholewidth=1.016 maxwidth=1.651 viatemplateguid#1={4ECBEE6A-5976-4D15-BCB2-50D932219331} viatemplateguid#2={AD42ABF7-9BEB-4345-B8C3-3A385202ECE7} viatemplateguid#3={461C434E-C8D4-4135-A003-8F82BFB8545A} viatemplateguid#4={D7946A99-C46F-4E40-8381-522DB26A846C} viatemplateguid#5={51CDBDAC-4D00-48B2-AB26-3F061ED27015} viatemplatename#1=v50h20 viatemplatename#2=v165h102 viatemplatename#3=v61h20(3) viatemplatename#4=v61h20(4) viatemplatename#5=v86h41
RoutingVias ThermalPadVias [IsVia and InAnyComponent] p2: holewidth=0.2 width=0.5 viastyle="Through Hole" minholewidth=0.2 minwidth=0.5 maxholewidth=0.33 maxwidth=0.6
SilkToBoardRegionClearance [Not ((IsComment or IsDesignator) And (Hide <> 'False')) and not InRegion(1000,500,4000,800)] p1:
SilkToSilkClearance SilkToSilkClearance_Pb-FreeLogo [(HasFootprint('Pb-Free_Overlay_Medium') OR HasFootprint('Pb-Free_Overlay_Small')) vs (HasFootprint('Pb-Free_Overlay_Medium') OR HasFootprint('Pb-Free_Overlay_Small'))] p1: silktosilkclearance=0
SilkToSilkClearance [All] p2: silktosilkclearance=0.1
SilkToSolderMaskClearance SilkToComponentPadClearance [(IsPad or IsFill or IsRegion) and InAnycomponent] p1: minsilkscreentomaskgap=0.127 clearancetoexposedcopper=TRUE
SilkToSolderMaskClearance "Silk to Solder Mask Opening" [All] p2: minsilkscreentomaskgap=0.1 clearancetoexposedcopper=FALSE
SolderMaskExpansion [All] p1: expansion=0.05 istentingtop=FALSE
SupplyNets "Schematic Supply Nets_8" [InNet('12Vs')] p1: voltage=0.000
SupplyNets "Schematic Supply Nets_7" [InNet('VBUS')] p2: voltage=0.000
SupplyNets "Schematic Supply Nets_6" [InNet('3V3')] p3: voltage=0.000
SupplyNets "Schematic Supply Nets_5" [InNet('D-')] p4: voltage=0.000
SupplyNets "Schematic Supply Nets_4" [InNet('2V')] p5: voltage=0.000
SupplyNets "Schematic Supply Nets_3" [InNet('12Vp')] p6: voltage=0.000
SupplyNets "Schematic Supply Nets_2" [InNet('VBUS_28V')] p7: voltage=0.000
SupplyNets "Schematic Supply Nets_1" [InNet('5V')] p8: voltage=0.000
SupplyNets "Schematic Supply Nets" [InNet('GND')] p9: voltage=0.000
UnRoutedNet [All] p1: checkbadconnections=TRUE
Width [All] p1: maxlimit=2.54 minlimit=0.152 preferedwidth=0.254 checkconnectedcopper=TRUE
13 further rules are at their usual default settings.

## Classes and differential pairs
component class Logo: Logo1
net class PF_Nets: 3V3 12Vs BP5H_PF BP5L_PF CS_HiSide_PF CS_InPhase_PF CS_PF D6 D- DHL_PF DLH_PF EN_HI_PF GND HVIN_PF NetC37_PF_2 NetC41_PF_2 NetC43_PF_1 NetC46_PF_2 NetC47_PF_1 NetC51_PF_2 NetC54_PF_1 NetC54_PF_2 NetC56_PF_2 NetD8_PF_2 NetD9_PF_2 NetR79_PF_2 NetR81_PF_1 NetR93_PF_1 NetR95_PF_2 Phase_PF PWM_FH PWM_FL PWM_LI_PF SW_PF V_PH_PF VBUS
net class PE_Nets: 3V3 12Vs BP5H_PE BP5L_PE CS_HiSide_PE CS_InPhase_PE CS_PE D5 D- DHL_PE DLH_PE EN_HI_PE GND HVIN_PE NetC37_PE_2 NetC41_PE_2 NetC43_PE_1 NetC46_PE_2 NetC47_PE_1 NetC51_PE_2 NetC54_PE_1 NetC54_PE_2 NetC56_PE_2 NetD8_PE_2 NetD9_PE_2 NetR79_PE_2 NetR81_PE_1 NetR93_PE_1 NetR95_PE_2 Phase_PE PWM_EH PWM_EL PWM_LI_PE SW_PE V_PH_PE VBUS
net class PD_Nets: 3V3 12Vs BP5H_PD BP5L_PD CS_HiSide_PD CS_InPhase_PD CS_PD D4 D- DHL_PD DLH_PD EN_HI_PD GND HVIN_PD NetC37_PD_2 NetC41_PD_2 NetC43_PD_1 NetC46_PD_2 NetC47_PD_1 NetC51_PD_2 NetC54_PD_1 NetC54_PD_2 NetC56_PD_2 NetD8_PD_2 NetD9_PD_2 NetR79_PD_2 NetR81_PD_1 NetR93_PD_1 NetR95_PD_2 Phase_PD PWM_DH PWM_DL PWM_LI_PD SW_PD V_PH_PD VBUS
net class PC_Nets: 3V3 12Vs BP5H_PC BP5L_PC CS_HiSide_PC CS_InPhase_PC CS_PC D3 D- DHL_PC DLH_PC EN_HI_PC GND HVIN_PC NetC37_PC_2 NetC41_PC_2 NetC43_PC_1 NetC46_PC_2 NetC47_PC_1 NetC51_PC_2 NetC54_PC_1 NetC54_PC_2 NetC56_PC_2 NetD8_PC_2 NetD9_PC_2 NetR79_PC_2 NetR81_PC_1 NetR93_PC_1 NetR95_PC_2 Phase_PC PWM_CH PWM_CL PWM_LI_PC SW_PC V_PH_PC VBUS
net class PB_Nets: 3V3 12Vs BP5H_PB BP5L_PB CS_HiSide_PB CS_InPhase_PB CS_PB D2 D- DHL_PB DLH_PB EN_HI_PB GND HVIN_PB NetC37_PB_2 NetC41_PB_2 NetC43_PB_1 NetC46_PB_2 NetC47_PB_1 NetC51_PB_2 NetC54_PB_1 NetC54_PB_2 NetC56_PB_2 NetD8_PB_2 NetD9_PB_2 NetR79_PB_2 NetR81_PB_1 NetR93_PB_1 NetR95_PB_2 Phase_PB PWM_BH PWM_BL PWM_LI_PB SW_PB V_PH_PB VBUS
net class PA_Nets: 3V3 12Vs BP5H_PA BP5L_PA CS_HiSide_PA CS_InPhase_PA CS_PA D1 D- DHL_PA DLH_PA EN_HI_PA GND HVIN_PA NetC37_PA_2 NetC41_PA_2 NetC43_PA_1 NetC46_PA_2 NetC47_PA_1 NetC51_PA_2 NetC54_PA_1 NetC54_PA_2 NetC56_PA_2 NetD8_PA_2 NetD9_PA_2 NetR79_PA_2 NetR81_PA_1 NetR93_PA_1 NetR95_PA_2 Phase_PA PWM_AH PWM_AL PWM_LI_PA SW_PA V_PH_PA VBUS
component class U_TempSensing: C32 C33 C34 C45 C57 C58 C59 C60 Q2 R96 R97 R98 R99 R100 R101 R103 R104 R105 R106 R107 R108 U8
component class "Mounting Holes": H1 H2 H3 H4
channel class PowerStage: PA PB PC PD PE PF
component class U_Interface: C1 C2 C3 C4 C5 C6 C7 C8 C9 C10 C11 C12 C13 C14 C15 C16 C17 C18 C19 C28 C61 D1 D2 D3 D4 D5 D6 D7 D16 J1 J2 J3 J4 J5 J6 J7 J8 R1 R2 R3 R4 R5 R6 R7 R8 R9 R10 R11 R12 R13 R14 R15 R16 R17 R18 R19 R20 R21 R22 R23 R24 R25 R26 R27 R28 R29 R30 R31 R32 R33 R34 R35 R36 R37 R38 R39 R40 R41 R42 R43 R44 R45 R46 R47 R48 R49 R50 R51 R52 R53 R56 R57 R72 R109 R113 R115 R116 R117 R118 U1 U2
component class U_PowerSupply: C20 C21 C22 C23 C24 C25 C26 C27 C29 C30 D10 D12 D13 D14 D17 J11 J12 J13 J14 J15 R54 R55 R58 R59 R60 R61 R62 R63 R64 R65 R66 R67 R68 R69 R70 R71 R73 R74 R102 R110 R111 R112 R114 TP1 TP2 TP3 TP4 TP5 TP10 TPS1 TPS1C TPS2 TPS2C U4
component class PF: C31_PF C35_PF C36_PF C37_PF C38_PF C39_PF C40_PF C41_PF C42_PF C43_PF C44_PF C46_PF C47_PF C48_PF C49_PF C50_PF C51_PF C52_PF C53_PF C54_PF C55_PF C56_PF D8_PF D9_PF D11_PF D15_PF J17_PF Q1_PF R75_PF R76_PF R77_PF R78_PF R79_PF R80_PF R81_PF R82_PF R83_PF R84_PF R85_PF R86_PF R87_PF R88_PF R89_PF R90_PF R91_PF R92_PF R93_ R94_PF R95_PF TP6_PF TP7_PF TP8_PF TP9_PF TP10_PF TP11_PF TP12_PF TP13_PF TP14_PF TP16_PF TP17_PF TP18_PF U5_PF U6_PF U7_PF
component class PE: C31_PE C35_PE C36_PE C37_PE C38_PE C39_PE C40_PE C41_PE C42_PE C43_PE C44_PE C46_PE C47_PE C48_PE C49_PE C50_PE C51_PE C52_PE C53_PE C54_PE C55_PE C56_PE D8_PE D9_PE D11_PE D15_PE J17_PE Q1_PE R75_PE R76_PE R77_PE R78_PE R79_PE R80_PE R81_PE R82_PE R83_PE R84_PE R85_PE R86_PE R87_PE R88_PE R89_PE R90_PE R91_PE R92_PE R93_ R94_PE R95_PE TP6_PE TP7_PE TP8_PE TP9_PE TP10_PE TP11_PE TP12_PE TP13_PE TP14_PE TP16_PE TP17_PE TP18_PE U5_PE U6_PE U7_PE
component class PD: C31_PD C35_PD C36_PD C37_PD C38_PD C39_PD C40_PD C41_PD C42_PD C43_PD C44_PD C46_PD C47_PD C48_PD C49_PD C50_PD C51_PD C52_PD C53_PD C54_PD C55_PD C56_PD D8_PD D9_PD D11_PD D15_PD J17_PD Q1_PD R75_PD R76_PD R77_PD R78_PD R79_PD R80_PD R81_PD R82_PD R83_PD R84_PD R85_PD R86_PD R87_PD R88_PD R89_PD R90_PD R91_PD R92_PD R93_ R94_PD R95_PD TP6_PD TP7_PD TP8_PD TP9_PD TP10_PD TP11_PD TP12_PD TP13_PD TP14_PD TP16_PD TP17_PD TP18_PD U5_PD U6_PD U7_PD
component class PC: C31_PC C35_PC C36_PC C37_PC C38_PC C39_PC C40_PC C41_PC C42_PC C43_PC C44_PC C46_PC C47_PC C48_PC C49_PC C50_PC C51_PC C52_PC C53_PC C54_PC C55_PC C56_PC D8_PC D9_PC D11_PC D15_PC J17_PC Q1_PC R75_PC R76_PC R77_PC R78_PC R79_PC R80_PC R81_PC R82_PC R83_PC R84_PC R85_PC R86_PC R87_PC R88_PC R89_PC R90_PC R91_PC R92_PC R93_ R94_PC R95_PC TP6_PC TP7_PC TP8_PC TP9_PC TP10_PC TP11_PC TP12_PC TP13_PC TP14_PC TP16_PC TP17_PC TP18_PC U5_PC U6_PC U7_PC
component class PB: C31_PB C35_PB C36_PB C37_PB C38_PB C39_PB C40_PB C41_PB C42_PB C43_PB C44_PB C46_PB C47_PB C48_PB C49_PB C50_PB C51_PB C52_PB C53_PB C54_PB C55_PB C56_PB D8_PB D9_PB D11_PB D15_PB J17_PB Q1_PB R75_PB R76_PB R77_PB R78_PB R79_PB R80_PB R81_PB R82_PB R83_PB R84_PB R85_PB R86_PB R87_PB R88_PB R89_PB R90_PB R91_PB R92_PB R93_ R94_PB R95_PB TP6_PB TP7_PB TP8_PB TP9_PB TP10_PB TP11_PB TP12_PB TP13_PB TP14_PB TP16_PB TP17_PB TP18_PB U5_PB U6_PB U7_PB
component class PA: C31_PA C35_PA C36_PA C37_PA C38_PA C39_PA C40_PA C41_PA C42_PA C43_PA C44_PA C46_PA C47_PA C48_PA C49_PA C50_PA C51_PA C52_PA C53_PA C54_PA C55_PA C56_PA D8_PA D9_PA D11_PA D15_PA J17_PA Q1_PA R75_PA R76_PA R77_PA R78_PA R79_PA R80_PA R81_PA R82_PA R83_PA R84_PA R85_PA R86_PA R87_PA R88_PA R89_PA R90_PA R91_PA R92_PA R93_ R94_PA R95_PA TP6_PA TP7_PA TP8_PA TP9_PA TP10_PA TP11_PA TP12_PA TP13_PA TP14_PA TP16_PA TP17_PA TP18_PA U5_PA U6_PA U7_PA
component class Header: J12 J14 J15 J17_PA J17_PB J17_PC J17_PD J17_PE J17_PF
component class U_Hardware: 5 FID1 FID2 FID3 H1 H2 H3 H4 LBL1 Logo3 Logo6 Logo7 ZZ1 ZZ2 ZZ3 ZZ4
component class FiducialMark: FID1 FID2 FID3
component class AssemblyNote: ZZ1 ZZ2 ZZ3 ZZ4
component class Label: LBL1

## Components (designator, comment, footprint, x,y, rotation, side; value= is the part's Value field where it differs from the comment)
5 "CAUTION HOT SURFACE" IEC_HotSurface_Small 91.48,38.616 r0 top
C1 "GRM188R71C104KA01D" 0603 156.671,88.636 r180 bottom locked value=0.1uF
C2 "GRM188R71C104KA01D" 0603 156.341,85.553 r180 bottom locked value=0.1uF
C3 "CMP-0006827-4" 0603 137.624,52.526 r180 bottom locked value=2200pF
C4 "CMP-0006827-4" 0603 140.57,48.295 r270 bottom locked value=2200pF
C5 "CMP-0006827-4" 0603 146.346,56.406 r0 bottom locked value=2200pF
C6 "CMP-0006827-4" 0603 148.902,57.237 r90 bottom locked value=2200pF
C7 "CMP-0006827-4" 0603 153.068,48.295 r270 bottom locked value=2200pF
C8 "CMP-0006827-4" 0603 153.855,57.237 r90 bottom locked value=2200pF
C9 "CMP-0006827-4" 0603 158.855,57.237 r90 bottom locked value=2200pF
C10 "CMP-0006827-4" 0603 163.57,57.237 r90 bottom locked value=2200pF
C11 "GRM188R71C104KA01D" 0603 92.366,88.75 r180 bottom locked value=0.1uF
C12 "GRM188R71C104KA01D" 0603 92.916,85.67 r180 bottom locked value=0.1uF
C13 "CMP-0006827-4" 0603 77.848,48.5 r270 bottom locked value=2200pF
C14 "CMP-0006827-4" 0603 83.181,57.236 r90 bottom locked value=2200pF
C15 "CMP-0006827-4" 0603 84.985,57.236 r90 top locked value=2200pF
C16 "CMP-0006827-4" 0603 85.207,48.39 r270 top value=2200pF
C17 "CMP-0006827-4" 0603 87.794,57.236 r90 bottom locked value=2200pF
C18 "CMP-0006827-4" 0603 93.682,56.436 r0 bottom locked value=2200pF
C19 "GRM188R71C333KA01D" 0603 162.912,61.926 r0 top locked value=0.033uF
C20 "GRM188R71C333KA01D" 0603 9.402,49.586 r90 top locked value=0.033uF
C21 "GRM188R72E102KW07D" 0603 4.997,45.508 r270 top locked value=1000pF
C22 "GRM188R71E474KA12D" 0603 9.608,33.642 r180 top locked value=0.47uF
C23 "12103C105KAT2A" 1210_150 16.142,66.274 r270 top value=1uF
C24 "C1210C106K3RACTU" 1210_280 11.183,87.725 r0 top locked value=10uF
C25 "GRM188R71C333KA01D" 0603 9.64,24.631 r90 top locked value=0.033uF
C26 "GRM188R72E102KW07D" 0603 4.648,18.49 r270 top locked value=1000pF
C27 "GRM188R71E474KA12D" 0603 9.921,8.684 r180 top locked value=0.47uF
C28 "CMP-0006827-4" 0603 74.25,52.5 r180 bottom value=2200pF
C29 "GRM188R72E471KW07D" 0603 10.069,55.847 r0 top locked value=470pF
C30 "C1210C106K3RACTU" 1210_280 3.626,60.556 r90 top value=10uF
C31_PA "GRM188R71C104KA01D" 0603 113.387,103.812 r0 top locked value=0.1uF (schematic designator C31)
C31_PB "GRM188R71C104KA01D" 0603 113.409,58.243 r0 top value=0.1uF (schematic designator C31)
C31_PC "GRM188R71C104KA01D" 0603 113.289,12.756 r0 top locked value=0.1uF (schematic designator C31)
C31_PD "GRM188R71C104KA01D" 0603 61.961,132.932 r180 top locked value=0.1uF (schematic designator C31)
C31_PE "GRM188R71C104KA01D" 0603 61.893,86.92 r180 top locked value=0.1uF (schematic designator C31)
C31_PF "GRM188R71C104KA01D" 0603 61.879,40.996 r180 top value=0.1uF (schematic designator C31)
C32 "885012206034" 0603 85.5,25.25 r0 bottom value=1000pF
C33 "885012206034" 0603 83,14.5 r0 bottom value=1000pF
C34 "885012206034" 0603 82.175,25.25 r180 bottom value=1000pF
C35_PA "GRM31CR72E104KW03L" 1206_180 133.591,105.643 r0 top locked value=0.1uF (schematic designator C35)
C35_PB "GRM31CR72E104KW03L" 1206_180 133.613,60.074 r0 top value=0.1uF (schematic designator C35)
C35_PC "GRM31CR72E104KW03L" 1206_180 133.493,14.587 r0 top locked value=0.1uF (schematic designator C35)
C35_PD "GRM31CR72E104KW03L" 1206_180 41.757,131.101 r180 top locked value=0.1uF (schematic designator C35)
C35_PE "GRM31CR72E104KW03L" 1206_180 41.689,85.089 r180 top locked value=0.1uF (schematic designator C35)
C35_PF "GRM31CR72E104KW03L" 1206_180 41.675,39.165 r180 top value=0.1uF (schematic designator C35)
C36_PA "GRM31CR72E104KW03L" 1206_180 119.848,105.821 r180 top locked value=0.1uF (schematic designator C36)
C36_PB "GRM31CR72E104KW03L" 1206_180 119.87,60.252 r180 top value=0.1uF (schematic designator C36)
C36_PC "GRM31CR72E104KW03L" 1206_180 119.75,14.766 r180 top locked value=0.1uF (schematic designator C36)
C36_PD "GRM31CR72E104KW03L" 1206_180 55.5,130.923 r0 top locked value=0.1uF (schematic designator C36)
C36_PE "GRM31CR72E104KW03L" 1206_180 55.432,84.911 r0 top locked value=0.1uF (schematic designator C36)
C36_PF "GRM31CR72E104KW03L" 1206_180 55.418,38.986 r0 top value=0.1uF (schematic designator C36)
C37_PA "0603ZC101KAT2A" 0603 118.098,109.631 r90 top locked value=100pF (schematic designator C37)
C37_PB "0603ZC101KAT2A" 0603 118.12,64.062 r90 top value=100pF (schematic designator C37)
C37_PC "0603ZC101KAT2A" 0603 118,18.576 r90 top locked value=100pF (schematic designator C37)
C37_PD "0603ZC101KAT2A" 0603 57.25,127.113 r270 top locked value=100pF (schematic designator C37)
C37_PE "0603ZC101KAT2A" 0603 57.182,81.101 r270 top locked value=100pF (schematic designator C37)
C37_PF "0603ZC101KAT2A" 0603 57.168,35.176 r270 top value=100pF (schematic designator C37)
C38_PA "CKG57NX7T2E335M500JH" CKG57N 133.283,99.331 r270 top locked value=3.3uF (schematic designator C38)
C38_PB "CKG57NX7T2E335M500JH" CKG57N 133.305,53.762 r270 top locked value=3.3uF (schematic designator C38)
C38_PC "CKG57NX7T2E335M500JH" CKG57N 133.185,8.275 r270 top locked value=3.3uF (schematic designator C38)
C38_PD "CKG57NX7T2E335M500JH" CKG57N 42.065,137.413 r90 top locked value=3.3uF (schematic designator C38)
C38_PE "CKG57NX7T2E335M500JH" CKG57N 41.996,91.401 r90 top locked value=3.3uF (schematic designator C38)
C38_PF "CKG57NX7T2E335M500JH" CKG57N 41.983,45.477 r90 top value=3.3uF (schematic designator C38)
C39_PA "CKG57NX7T2E335M500JH" CKG57N 127.128,99.331 r270 top locked value=3.3uF (schematic designator C39)
C39_PB "CKG57NX7T2E335M500JH" CKG57N 127.15,53.762 r270 top locked value=3.3uF (schematic designator C39)
C39_PC "CKG57NX7T2E335M500JH" CKG57N 127.03,8.275 r270 top locked value=3.3uF (schematic designator C39)
C39_PD "CKG57NX7T2E335M500JH" CKG57N 48.22,137.413 r90 top locked value=3.3uF (schematic designator C39)
C39_PE "CKG57NX7T2E335M500JH" CKG57N 48.152,91.401 r90 top locked value=3.3uF (schematic designator C39)
C39_PF "CKG57NX7T2E335M500JH" CKG57N 48.138,45.477 r90 top value=3.3uF (schematic designator C39)
C40_PA "CKG57NX7T2E335M500JH" CKG57N 120.972,99.331 r270 top locked value=3.3uF (schematic designator C40)
C40_PB "CKG57NX7T2E335M500JH" CKG57N 120.994,53.762 r270 top locked value=3.3uF (schematic designator C40)
C40_PC "CKG57NX7T2E335M500JH" CKG57N 120.874,8.275 r270 top locked value=3.3uF (schematic designator C40)
C40_PD "CKG57NX7T2E335M500JH" CKG57N 54.376,137.413 r90 top locked value=3.3uF (schematic designator C40)
C40_PE "CKG57NX7T2E335M500JH" CKG57N 54.308,91.401 r90 top locked value=3.3uF (schematic designator C40)
C40_PF "CKG57NX7T2E335M500JH" CKG57N 54.294,45.477 r90 top value=3.3uF (schematic designator C40)
C41_PA "0603ZC101KAT2A" 0603 119.848,111.416 r90 top locked value=100pF (schematic designator C41)
C41_PB "0603ZC101KAT2A" 0603 119.87,65.847 r90 top value=100pF (schematic designator C41)
C41_PC "0603ZC101KAT2A" 0603 119.75,20.36 r90 top locked value=100pF (schematic designator C41)
C41_PD "0603ZC101KAT2A" 0603 55.5,125.328 r270 top locked value=100pF (schematic designator C41)
C41_PE "0603ZC101KAT2A" 0603 55.432,79.316 r270 top locked value=100pF (schematic designator C41)
C41_PF "0603ZC101KAT2A" 0603 55.418,33.392 r270 top value=100pF (schematic designator C41)
C42_PA "0603ZC101KAT2A" 0603 118.098,112.994 r90 top locked value=100pF (schematic designator C42)
C42_PB "0603ZC101KAT2A" 0603 118.12,67.425 r90 top value=100pF (schematic designator C42)
C42_PC "0603ZC101KAT2A" 0603 118,21.938 r90 top locked value=100pF (schematic designator C42)
C42_PD "0603ZC101KAT2A" 0603 57.25,123.75 r270 top locked value=100pF (schematic designator C42)
C42_PE "0603ZC101KAT2A" 0603 57.182,77.738 r270 top locked value=100pF (schematic designator C42)
C42_PF "0603ZC101KAT2A" 0603 57.168,31.814 r270 top value=100pF (schematic designator C42)
C43_PA "GCM1885C1H150JA16D" 0603 108.533,118.646 r180 top locked value=15pF (schematic designator C43)
C43_PB "GCM1885C1H150JA16D" 0603 108.556,73.077 r180 top value=15pF (schematic designator C43)
C43_PC "GCM1885C1H150JA16D" 0603 108.436,27.59 r180 top locked value=15pF (schematic designator C43)
C43_PD "GCM1885C1H150JA16D" 0603 66.814,118.098 r0 top locked value=15pF (schematic designator C43)
C43_PE "GCM1885C1H150JA16D" 0603 66.746,72.086 r0 top locked value=15pF (schematic designator C43)
C43_PF "GCM1885C1H150JA16D" 0603 66.732,26.162 r0 top value=15pF (schematic designator C43)
C44_PA "CGA4J1X7R1E475K125AC" 0805L 136.638,124.713 r180 top value=4.7uF (schematic designator C44)
C44_PB "CGA4J1X7R1E475K125AC" 0805L 136.77,79.259 r180 top value=4.7uF (schematic designator C44)
C44_PC "CGA4J1X7R1E475K125AC" 0805L 136.637,33.651 r180 top locked value=4.7uF (schematic designator C44)
C44_PD "CGA4J1X7R1E475K125AC" 0805L 38.702,112.034 r0 top locked value=4.7uF (schematic designator C44)
C44_PE "CGA4J1X7R1E475K125AC" 0805L 38.67,65.962 r0 top locked value=4.7uF (schematic designator C44)
C44_PF "CGA4J1X7R1E475K125AC" 0805L 38.656,20.037 r0 top value=4.7uF (schematic designator C44)
C45 "885012206034" 0603 78.5,15.75 r90 bottom value=1000pF
C46_PA "08055C105K4Z2A" 0805_HV 137.55,120.262 r180 top value=1uF (schematic designator C46)
C46_PB "08055C105K4Z2A" 0805_HV 137.402,74.756 r180 top value=1uF (schematic designator C46)
C46_PC "08055C105K4Z2A" 0805_HV 137.419,29.252 r180 top locked value=1uF (schematic designator C46)
C46_PD "08055C105K4Z2A" 0805_HV 38.121,116.447 r0 top locked value=1uF (schematic designator C46)
C46_PE "08055C105K4Z2A" 0805_HV 37.936,70.314 r0 top locked value=1uF (schematic designator C46)
C46_PF "08055C105K4Z2A" 0805_HV 37.922,24.39 r0 top value=1uF (schematic designator C46)
C47_PA "CGA3E3X7R1H474K080AE" 0603 135.846,117.56 r270 top value=0.47uF (schematic designator C47)
C47_PB "CGA3E3X7R1H474K080AE" 0603 135.868,71.991 r270 top value=0.47uF (schematic designator C47)
C47_PC "CGA3E3X7R1H474K080AE" 0603 135.748,26.504 r270 top locked value=0.47uF (schematic designator C47)
C47_PD "CGA3E3X7R1H474K080AE" 0603 39.502,119.184 r90 top locked value=0.47uF (schematic designator C47)
C47_PE "CGA3E3X7R1H474K080AE" 0603 39.434,73.172 r90 top locked value=0.47uF (schematic designator C47)
C47_PF "CGA3E3X7R1H474K080AE" 0603 39.42,27.248 r90 top value=0.47uF (schematic designator C47)
C48_PA "CGA3E2NP01H470J080AA" 0603 136.357,126.528 r0 top value=47pF (schematic designator C48)
C48_PB "CGA3E2NP01H470J080AA" 0603 136.379,80.959 r0 top value=47pF (schematic designator C48)
C48_PC "CGA3E2NP01H470J080AA" 0603 136.259,35.472 r0 top locked value=47pF (schematic designator C48)
C48_PD "CGA3E2NP01H470J080AA" 0603 38.991,110.216 r180 top locked value=47pF (schematic designator C48)
C48_PE "CGA3E2NP01H470J080AA" 0603 38.923,64.204 r180 top locked value=47pF (schematic designator C48)
C48_PF "CGA3E2NP01H470J080AA" 0603 38.909,18.28 r180 top value=47pF (schematic designator C48)
C49_PA "CGA3E2NP01H470J080AA" 0603 136.364,131.411 r0 top value=47pF (schematic designator C49)
C49_PB "CGA3E2NP01H470J080AA" 0603 136.386,85.843 r0 top value=47pF (schematic designator C49)
C49_PC "CGA3E2NP01H470J080AA" 0603 136.266,40.356 r0 top locked value=47pF (schematic designator C49)
C49_PD "CGA3E2NP01H470J080AA" 0603 38.984,105.332 r180 top locked value=47pF (schematic designator C49)
C49_PE "CGA3E2NP01H470J080AA" 0603 38.916,59.32 r180 top locked value=47pF (schematic designator C49)
C49_PF "CGA3E2NP01H470J080AA" 0603 38.902,13.396 r180 top value=47pF (schematic designator C49)
C50_PA "GRM188R71C104KA01D" 0603 116.5,133.5 r90 top value=0.1uF (schematic designator C50)
C50_PB "GRM188R71C104KA01D" 0603 116.642,88.049 r90 top value=0.1uF (schematic designator C50)
C50_PC "GRM188R71C104KA01D" 0603 116.5,42.563 r90 top value=0.1uF (schematic designator C50)
C50_PD "GRM188R71C104KA01D" 0603 58.75,103.25 r270 top value=0.1uF (schematic designator C50)
C50_PE "GRM188R71C104KA01D" 0603 58.75,57.238 r270 top value=0.1uF (schematic designator C50)
C50_PF "GRM188R71C104KA01D" 0603 58.736,11.314 r270 top value=0.1uF (schematic designator C50)
C51_PA "08055C105K4Z2A" 0805_HV 137.533,122.577 r180 top value=1uF (schematic designator C51)
C51_PB "08055C105K4Z2A" 0805_HV 137.402,76.98 r180 top value=1uF (schematic designator C51)
C51_PC "08055C105K4Z2A" 0805_HV 137.419,31.476 r180 top locked value=1uF (schematic designator C51)
C51_PD "08055C105K4Z2A" 0805_HV 38.121,114.222 r0 top locked value=1uF (schematic designator C51)
C51_PE "08055C105K4Z2A" 0805_HV 37.936,68.09 r0 top locked value=1uF (schematic designator C51)
C51_PF "08055C105K4Z2A" 0805_HV 37.922,22.166 r0 top value=1uF (schematic designator C51)
C52_PA "08055C105K4Z2A" 0805_HV 131.287,130.675 r180 top value=1uF (schematic designator C52)
C52_PB "08055C105K4Z2A" 0805_HV 131.309,85.106 r180 top value=1uF (schematic designator C52)
C52_PC "08055C105K4Z2A" 0805_HV 131.189,39.619 r180 top locked value=1uF (schematic designator C52)
C52_PD "08055C105K4Z2A" 0805_HV 44.061,106.069 r0 top locked value=1uF (schematic designator C52)
C52_PE "08055C105K4Z2A" 0805_HV 43.993,60.057 r0 top locked value=1uF (schematic designator C52)
C52_PF "08055C105K4Z2A" 0805_HV 43.979,14.133 r0 top value=1uF (schematic designator C52)
C53_PA "GRM188R71C333KA01D" 0603 103.5,116.25 r270 top locked value=0.033uF (schematic designator C53)
C53_PB "GRM188R71C333KA01D" 0603 103.522,70.681 r270 top locked value=0.033uF (schematic designator C53)
C53_PC "GRM188R71C333KA01D" 0603 103.402,25.194 r270 top locked value=0.033uF (schematic designator C53)
C53_PD "GRM188R71C333KA01D" 0603 71.848,120.494 r90 top locked value=0.033uF (schematic designator C53)
C53_PE "GRM188R71C333KA01D" 0603 71.78,74.482 r90 top locked value=0.033uF (schematic designator C53)
C53_PF "GRM188R71C333KA01D" 0603 71.766,28.558 r90 top value=0.033uF (schematic designator C53)
C54_PA "GRM1885C1E152JA01D" 0603 113.98,128.981 r180 top locked value=1500pF (schematic designator C54)
C54_PB "GRM1885C1E152JA01D" 0603 114.002,83.412 r180 top value=1500pF (schematic designator C54)
C54_PC "GRM1885C1E152JA01D" 0603 113.882,37.925 r180 top locked value=1500pF (schematic designator C54)
C54_PD "GRM1885C1E152JA01D" 0603 61.368,107.763 r0 top locked value=1500pF (schematic designator C54)
C54_PE "GRM1885C1E152JA01D" 0603 61.3,61.751 r0 top locked value=1500pF (schematic designator C54)
C54_PF "GRM1885C1E152JA01D" 0603 61.286,15.827 r0 top value=1500pF (schematic designator C54)
C55_PA "08055C105K4Z2A" 0805_HV 133.083,113.794 r90 top value=1uF (schematic designator C55)
C55_PB "08055C105K4Z2A" 0805_HV 133.239,67.857 r90 top value=1uF (schematic designator C55)
C55_PC "08055C105K4Z2A" 0805_HV 133.172,22.646 r90 top locked value=1uF (schematic designator C55)
C55_PD "08055C105K4Z2A" 0805_HV 41.992,122.969 r270 top value=1uF (schematic designator C55)
C55_PE "08055C105K4Z2A" 0805_HV 41.924,76.957 r270 top value=1uF (schematic designator C55)
C55_PF "08055C105K4Z2A" 0805_HV 41.91,31.032 r270 top value=1uF (schematic designator C55)
C56_PA "GRM188R71C104KA01D" 0603 111.469,131.872 r90 top value=0.1uF (schematic designator C56)
C56_PB "GRM188R71C104KA01D" 0603 111.403,86.318 r90 top value=0.1uF (schematic designator C56)
C56_PC "GRM188R71C104KA01D" 0603 111.391,40.816 r90 top value=0.1uF (schematic designator C56)
C56_PD "GRM188R71C104KA01D" 0603 63.879,105.073 r270 top value=0.1uF (schematic designator C56)
C56_PE "GRM188R71C104KA01D" 0603 63.811,59 r270 top value=0.1uF (schematic designator C56)
C56_PF "GRM188R71C104KA01D" 0603 63.797,13.076 r270 top value=0.1uF (schematic designator C56)
C57 "GRM188R71C104KA01D" 0603 84.5,19.944 r90 bottom value=0.1uF
C58 "885012206034" 0603 75.75,23.29 r180 bottom value=1000pF
C59 "885012206034" 0603 81.7,11.564 r270 bottom value=1000pF
C60 "885012206034" 0603 79.005,25.25 r180 bottom value=1000pF
C61 "CMP-0006827-4" 0603 101.75,56.949 r90 bottom value=2200pF
D1 "1PS79SB70,115" SOD-523 165.29,56.914 r270 bottom locked value=70V
D2 "1PS79SB70,115" SOD-523 155.497,56.914 r270 bottom locked value=70V
D3 "1PS79SB70,115" SOD-523 160.447,56.914 r270 bottom locked value=70V
D4 "1PS79SB70,115" SOD-523 154.577,48.619 r90 bottom locked value=70V
D5 "1PS79SB70,115" SOD-523 84.709,56.912 r270 bottom locked value=70V
D6 "1PS79SB70,115" SOD-523 93.489,57.919 r0 bottom locked value=70V
D7 "1PS79SB70,115" SOD-523 88.307,48.428 r90 top value=70V
D8_PA "SS1200-LTP" SMA 140.413,117.56 r0 top value=200V (schematic designator D8)
D8_PB "SS1200-LTP" SMA 140.435,71.991 r0 top value=200V (schematic designator D8)
D8_PC "SS1200-LTP" SMA 140.315,26.504 r0 top locked value=200V (schematic designator D8)
D8_PD "SS1200-LTP" SMA 34.935,119.184 r180 top locked value=200V (schematic designator D8)
D8_PE "SS1200-LTP" SMA 34.867,73.172 r180 top locked value=200V (schematic designator D8)
D8_PF "SS1200-LTP" SMA 34.853,27.248 r180 top value=200V (schematic designator D8)
D9_PA "SS1200-LTP" SMA 140.413,114.1 r0 top value=200V (schematic designator D9)
D9_PB "SS1200-LTP" SMA 140.435,68.531 r0 top value=200V (schematic designator D9)
D9_PC "SS1200-LTP" SMA 140.315,23.045 r0 top locked value=200V (schematic designator D9)
D9_PD "SS1200-LTP" SMA 34.935,122.644 r180 top value=200V (schematic designator D9)
D9_PE "SS1200-LTP" SMA 34.867,76.632 r180 top locked value=200V (schematic designator D9)
D9_PF "SS1200-LTP" SMA 34.853,30.707 r180 top value=200V (schematic designator D9)
D10 "APT2012LZGCK" APT2012_Green 14.75,76.297 r90 top locked value=Green
D11_PA "BZT52B12-E3-08" SOD-123 138.773,110.888 r180 top value=12V (schematic designator D11)
D11_PB "BZT52B12-E3-08" SOD-123 138.933,65.344 r180 top value=12V (schematic designator D11)
D11_PC "BZT52B12-E3-08" SOD-123 138.674,19.833 r180 top locked value=12V (schematic designator D11)
D11_PD "BZT52B12-E3-08" SOD-123 36.574,125.855 r0 top value=12V (schematic designator D11)
D11_PE "BZT52B12-E3-08" SOD-123 36.507,79.843 r0 top locked value=12V (schematic designator D11)
D11_PF "BZT52B12-E3-08" SOD-123 36.493,33.919 r0 top value=12V (schematic designator D11)
D12 "APT2012LZGCK" APT2012_Green 27.432,91.738 r90 top locked value=Green
D13 "APT2012LZGCK" APT2012_Green 23.5,43.298 r90 top value=Green
D14 "APT2012LZGCK" APT2012_Green 19.5,11.979 r90 top value=Green
D15_PA "DFLS1200-7" PowerDI123 122.545,124.928 r90 top value=200V (schematic designator D15)
D15_PB "DFLS1200-7" PowerDI123 122.567,79.359 r90 top value=200V (schematic designator D15)
D15_PC "DFLS1200-7" PowerDI123 122.447,33.872 r90 top locked value=200V (schematic designator D15)
D15_PD "DFLS1200-7" PowerDI123 52.803,111.816 r270 top locked value=200V (schematic designator D15)
D15_PE "DFLS1200-7" PowerDI123 52.735,65.804 r270 top locked value=200V (schematic designator D15)
D15_PF "DFLS1200-7" PowerDI123 52.721,19.88 r270 top value=200V (schematic designator D15)
D16 "1PS79SB70,115" SOD-523 103.75,56.149 r180 bottom value=70V
D17 "APT2012LZGCK" APT2012_Green 23.5,50.25 r90 top value=Green
FID1 "Fiducial" Fiducial10-20 5,90 r0 top
FID2 "Fiducial" Fiducial10-20 167,135.5 r0 top
FID3 "Fiducial" Fiducial10-20 165,11.25 r0 top
H1 "NY PMS 440 0025 PH" "NY PMS 440 0025 PH" 5.25,147.221 r0 top
H2 "NY PMS 440 0025 PH" "NY PMS 440 0025 PH" 172.5,147.221 r0 top
H3 "NY PMS 440 0025 PH" "NY PMS 440 0025 PH" 172.5,5.25 r0 top
H4 "NY PMS 440 0025 PH" "NY PMS 440 0025 PH" 26.531,5.447 r0 top
J1 "SSW-110-23-F-S" CONN_SSW-110-23-F-S 152.606,51.602 r0 top locked
J2 "SSW-110-23-F-S" CONN_SSW-110-23-F-S 152.606,97.322 r180 top locked
J3 "SSW-110-23-F-S" CONN_SSW-110-23-F-S 152.606,54.142 r0 top locked
J4 "SSW-110-23-F-S" CONN_SSW-110-23-F-S 152.606,94.782 r180 top locked
J5 "SSW-110-23-F-S" CONN_SSW-110-23-F-S 89.106,51.602 r0 top
J6 "SSW-110-23-F-S" CONN_SSW-110-23-F-S 89.106,97.322 r180 top locked
J7 "SSW-110-23-F-S" CONN_SSW-110-23-F-S 89.106,54.142 r0 top locked
J8 "SSW-110-23-F-S" CONN_SSW-110-23-F-S 89.106,94.782 r180 top locked
J9 "OSTTC032162" On-Shore_OSTTC032162 92.216,72.77 r90 top locked
J10 "OSTTC032162" On-Shore_OSTTC032162 83.227,72.829 r270 top locked
J11 "OSTTC022162" On-Shore_OSTTC022162 67,145 r180 top
J12 "TSW-103-07-G-S" TSW-103-07-G-S 19,137.25 r180 top locked
J13 "OSTTC022162" On-Shore_OSTTC022162 18.25,145 r180 top
J14 "PEC06SAAN" Sullins_PEC06SAAN 18.62,108.925 r270 top locked
J15 "PEC02SAAN" CONN_PEC02SAAN 18.62,94.955 r270 top locked
J17_PA "TSW-103-07-G-S" TSW-103-07-G-S 94.878,105.821 r0 top locked (schematic designator J17)
J17_PB "TSW-103-07-G-S" TSW-103-07-G-S 94.9,60.252 r0 top locked (schematic designator J17)
J17_PC "TSW-103-07-G-S" TSW-103-07-G-S 94.78,14.766 r0 top (schematic designator J17)
J17_PD "TSW-103-07-G-S" TSW-103-07-G-S 80.47,130.923 r180 top locked (schematic designator J17)
J17_PE "TSW-103-07-G-S" TSW-103-07-G-S 80.402,84.911 r180 top locked (schematic designator J17)
J17_PF "TSW-103-07-G-S" TSW-103-07-G-S 80.388,38.986 r180 top (schematic designator J17)
LBL1 "Size: 0.65\" x 0.20 \"" Label_650x200 152,5 r0 top
Logo1 "Texas Instruments" TI_Stacked_Overlay_Small 159.423,25.904 r90 top
Logo2 "CE Mark" CE_Mark_5mm 171.923,18.654 r90 top
Logo3 "WEEE logo" WEEE_Minimum 165.673,19.654 r0 top
LOGO4 "CAUTION HOT SURFACE" IEC_HotSurface_Small 88.25,116.264 r180 top
Logo6 "FCC disclaimer" FCC_disclaimer -2,93.25 r0 top
Logo7 "Pb-Free Symbol" Pb-Free_Overlay_Small 74.038,6.75 r0 top
Q1_PA "MMBT3904LP" DIODES_X1-DFN1006-3 123.228,118.51 r270 top value="40 V" (schematic designator Q1)
Q1_PB "MMBT3904LP" DIODES_X1-DFN1006-3 123.396,72.866 r270 top value="40 V" (schematic designator Q1)
Q1_PC "MMBT3904LP" DIODES_X1-DFN1006-3 123.401,27.572 r270 top value="40 V" (schematic designator Q1)
Q1_PD "MMBT3904LP" DIODES_X1-DFN1006-3 51.974,118.188 r90 top value="40 V" (schematic designator Q1)
Q1_PE "MMBT3904LP" DIODES_X1-DFN1006-3 51.905,72.592 r90 top value="40 V" (schematic designator Q1)
Q1_PF "MMBT3904LP" DIODES_X1-DFN1006-3 51.892,26.298 r90 top value="40 V" (schematic designator Q1)
Q2 "MMBT3904LP" DIODES_X1-DFN1006-3 86.75,3.25 r270 bottom value="40 V"
R1 "RC0603JR-070RL" 0603 161.386,87.709 r270 top locked value=0
R2 "RC0603JR-070RL" 0603 162.25,84.747 r180 top locked value=0
R3 "RC0603FR-0720RL" 0603 162.013,57.237 r270 bottom locked value=20.0
R4 "RC0603FR-0720RL" 0603 157.112,57.237 r270 bottom locked value=20.0
R5 "RC0603FR-0720RL" 0603 152.242,57.237 r270 bottom locked value=20.0
R6 "RC0603FR-0720RL" 0603 151.336,48.295 r90 bottom locked value=20.0
R7 "RC0603FR-0720RL" 0603 150.583,57.237 r270 bottom locked value=20.0
R8 "RC0603FR-0710KL" 0603 159.316,82 r0 top locked value=10.0k
R9 "RC0603FR-0710KL" 0603 162.25,90.683 r180 top locked value=10.0k
R10 "RC0603FR-0720RL" 0603 142.729,56.406 r0 bottom locked value=20.0
R11 "RC0603FR-0720RL" 0603 142.157,48.295 r90 bottom locked value=20.0
R12 "RC0603FR-0720RL" 0603 137.624,54.123 r0 bottom value=20.0
R13 "RC0603FR-0710KL" 0603 163.797,91.109 r90 bottom locked value=10.0k
R14 "RC0603FR-0720RL" 0603 146,49.169 r0 bottom locked value=20.0
R15 "RC0603FR-0710KL" 0603 161.972,91.109 r90 bottom locked value=10.0k
R16 "RC0603FR-0710KL" 0603 160.148,91.109 r90 bottom locked value=10.0k
R17 "RC0603FR-0710KL" 0603 158.323,91.109 r90 bottom locked value=10.0k
R18 "RC0603FR-0710KL" 0603 156.498,91.109 r90 bottom locked value=10.0k
R19 "RC0603FR-0710KL" 0603 154.673,91.109 r90 bottom locked value=10.0k
R20 "RC0603FR-0710KL" 0603 159.889,86.909 r270 bottom locked value=10.0k
R21 "RC0603FR-0710KL" 0603 158.55,80.328 r90 bottom locked value=10.0k
R22 "RC0603FR-0710KL" 0603 156.623,80.328 r90 bottom locked value=10.0k
R23 "RC0603FR-0710KL" 0603 154.696,80.328 r90 bottom locked value=10.0k
R24 "RC0603FR-0710KL" 0603 152.769,80.328 r90 bottom locked value=10.0k
R25 "RC0603FR-0710KL" 0603 153.471,87.709 r270 bottom locked value=10.0k
R26 "RC0603FR-0710KL" 0603 149.968,90.682 r0 top value=10.0k
R27 "RC0603FR-0710KL" 0603 150.768,91.133 r90 bottom locked value=10.0k
R28 "RC0603FR-0710KL" 0603 152.765,91.109 r90 bottom locked value=10.0k
R29 "RC0603JR-070RL" 0603 97.681,87.709 r270 top locked value=0
R30 "RC0603JR-070RL" 0603 98.329,84.747 r180 top locked value=0
R31 "RC0603FR-0720RL" 0603 90.376,56.436 r0 bottom locked value=20.0
R32 "RC0603FR-0720RL" 0603 86.259,57.236 r270 bottom locked value=20.0
R33 "RC0603FR-0720RL" 0603 86.819,48.39 r90 top value=20.0
R34 "RC0603FR-0720RL" 0603 83.253,57.236 r270 top locked value=20.0
R35 "RC0603FR-0710KL" 0603 95.206,82 r0 top locked value=10.0k
R36 "RC0603FR-0710KL" 0603 98.389,90.682 r0 top locked value=10.0k
R37 "RC0603FR-0720RL" 0603 81.58,57.236 r270 bottom locked value=20.0
R38 "RC0603FR-0720RL" 0603 79.5,48.5 r90 bottom locked value=20.0
R39 "RC0603FR-0710KL" 0603 100.463,91.284 r90 bottom locked value=10.0k
R40 "RC0603FR-0710KL" 0603 98.672,91.284 r90 bottom locked value=10.0k
R41 "RC0603FR-0710KL" 0603 96.88,91.284 r90 bottom locked value=10.0k
R42 "RC0603FR-0710KL" 0603 95.088,91.284 r90 bottom locked value=10.0k
R43 "RC0603FR-0710KL" 0603 93.296,91.284 r90 bottom locked value=10.0k
R44 "RC0603FR-0710KL" 0603 91.505,91.284 r90 bottom locked value=10.0k
R45 "RC0603FR-0710KL" 0603 95.206,87.635 r270 bottom locked value=10.0k
R46 "RC0603FR-0710KL" 0603 94.473,80.935 r90 bottom locked value=10.0k
R47 "RC0603FR-0710KL" 0603 92.651,80.935 r90 bottom locked value=10.0k
R48 "RC0603FR-0710KL" 0603 90.83,80.935 r90 bottom locked value=10.0k
R49 "RC0603FR-0710KL" 0603 89.009,80.935 r90 bottom locked value=10.0k
R50 "RC0603FR-0710KL" 0603 89.443,87.635 r270 bottom locked value=10.0k
R51 "RC0603FR-0710KL" 0603 86,90.682 r0 top locked value=10.0k
R52 "RC0603FR-0710KL" 0603 89.713,91.284 r90 bottom locked value=10.0k
R53 "RC0603FR-0710KL" 0603 87.921,91.284 r90 bottom locked value=10.0k
R54 "CRCW060349K9FKEA" 0603 15.985,46.371 r90 top locked value=49.9k
R55 "RC0603FR-0710KL" 0603 12.992,33.642 r0 top locked value=10.0k
R56 "RC0603FR-07100KL" 0603 159.331,61.928 r180 top locked value=100k
R57 "RC0603FR-074K22L" 0603 162.912,63.928 r180 top locked value=4.22k
R58 "CRCW060340K2FKEA" 0603 17.725,44.708 r90 top locked value=40.2k
R59 "CRCW060349R9FKEA" 0603 11.132,31.892 r180 top locked value=49.9
R60 "CRCW0603442KFKEA" 0603 7.712,49.586 r270 top locked value=442k
R61 "CRCW060313K3FKEA" 0603 7.712,31.892 r0 top locked value=13.3k
R62 "CRCW060320K0FKEA" 0603 4.997,42.298 r90 top locked value=20.0k
R63 "CRCW06031K82FKEA" 0603 6.188,33.642 r0 top locked value=1.82k
R64 "CRCW060349K9FKEA" 0603 16.429,21.586 r90 top locked value=49.9k
R65 "RC0603FR-0710KL" 0603 13.341,8.684 r0 top locked value=10.0k
R66 "CRCW060340K2FKEA" 0603 18.354,19.777 r90 top locked value=40.2k
R67 "CRCW060349R9FKEA" 0603 11.617,7.069 r180 top locked value=49.9
R68 "CRCW0603442KFKEA" 0603 8.004,24.641 r90 top locked value=442k
R69 "CRCW06034K53FKEA" 0603 8.127,7.069 r0 top locked value=4.53k
R70 "CRCW060320K0FKEA" 0603 4.648,15.04 r90 top locked value=20.0k
R71 "CRCW06031K00FKEA" 0603 6.604,8.646 r180 top locked value=1.00k
R72 "RC0603FR-0720RL" 0603 99.925,56.949 r270 bottom value=20.0
R73 "CRCW06035K49FKEA" 0603 9.992,53.999 r180 top locked value=5.49k
R74 "CRCW06038K45FKEA" 0603 12.75,55 r270 top locked value=8.45k
R75_PA "RC0603JR-070RL" 0603 122.403,110.594 r180 top locked value=0 (schematic designator R75)
R75_PB "RC0603JR-070RL" 0603 122.425,65.025 r180 top value=0 (schematic designator R75)
R75_PC "RC0603JR-070RL" 0603 122.305,19.538 r180 top locked value=0 (schematic designator R75)
R75_PD "RC0603JR-070RL" 0603 52.945,126.15 r0 top locked value=0 (schematic designator R75)
R75_PE "RC0603JR-070RL" 0603 52.876,80.138 r0 top locked value=0 (schematic designator R75)
R75_PF "RC0603JR-070RL" 0603 52.863,34.214 r0 top value=0 (schematic designator R75)
R76_PA "CRE2512-FZ-R005E-3" CRE2512-R5_R9 126.507,111.487 r270 top locked value=0.005 (schematic designator R76)
R76_PB "CRE2512-FZ-R005E-3" CRE2512-R5_R9 126.529,65.918 r270 top value=0.005 (schematic designator R76)
R76_PC "CRE2512-FZ-R005E-3" CRE2512-R5_R9 126.409,20.431 r270 top locked value=0.005 (schematic designator R76)
R76_PD "CRE2512-FZ-R005E-3" CRE2512-R5_R9 48.841,125.257 r90 top locked value=0.005 (schematic designator R76)
R76_PE "CRE2512-FZ-R005E-3" CRE2512-R5_R9 48.773,79.245 r90 top locked value=0.005 (schematic designator R76)
R76_PF "CRE2512-FZ-R005E-3" CRE2512-R5_R9 48.759,33.321 r90 top value=0.005 (schematic designator R76)
R77_PA "RC0603JR-070RL" 0603 122.403,112.248 r180 top value=0 (schematic designator R77)
R77_PB "RC0603JR-070RL" 0603 122.425,66.679 r180 top value=0 (schematic designator R77)
R77_PC "RC0603JR-070RL" 0603 122.305,21.193 r180 top locked value=0 (schematic designator R77)
R77_PD "RC0603JR-070RL" 0603 52.945,124.495 r0 top locked value=0 (schematic designator R77)
R77_PE "RC0603JR-070RL" 0603 52.876,78.484 r0 top locked value=0 (schematic designator R77)
R77_PF "RC0603JR-070RL" 0603 52.863,32.559 r0 top value=0 (schematic designator R77)
R78_PA "RC0603FR-072R1L" 0603 140.374,122.324 r90 top value=2.10 (schematic designator R78)
R78_PB "RC0603FR-072R1L" 0603 140.396,76.755 r90 top value=2.10 (schematic designator R78)
R78_PC "RC0603FR-072R1L" 0603 140.276,31.269 r90 top locked value=2.10 (schematic designator R78)
R78_PD "RC0603FR-072R1L" 0603 34.974,114.419 r270 top locked value=2.10 (schematic designator R78)
R78_PE "RC0603FR-072R1L" 0603 34.906,68.408 r270 top locked value=2.10 (schematic designator R78)
R78_PF "RC0603FR-072R1L" 0603 34.892,22.483 r270 top value=2.10 (schematic designator R78)
R79_PA "RC0603JR-070RL" 0603 112.181,118.644 r0 top locked value=0 (schematic designator R79)
R79_PB "RC0603JR-070RL" 0603 112.203,73.075 r0 top value=0 (schematic designator R79)
R79_PC "RC0603JR-070RL" 0603 112.083,27.589 r0 top locked value=0 (schematic designator R79)
R79_PD "RC0603JR-070RL" 0603 63.167,118.1 r180 top locked value=0 (schematic designator R79)
R79_PE "RC0603JR-070RL" 0603 63.099,72.088 r180 top locked value=0 (schematic designator R79)
R79_PF "RC0603JR-070RL" 0603 63.085,26.163 r180 top value=0 (schematic designator R79)
R80_PA "RC0603FR-072R1L" 0603 144.348,115.603 r90 top value=2.10 (schematic designator R80)
R80_PB "RC0603FR-072R1L" 0603 144.37,70.034 r90 top value=2.10 (schematic designator R80)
